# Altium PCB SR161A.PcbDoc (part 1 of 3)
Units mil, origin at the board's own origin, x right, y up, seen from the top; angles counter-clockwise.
Board outline 3150 x 3740 mil, 6 copper layers (Top Layer, Signal Layer 1, Signal Layer 2, Signal Layer 3, Signal Layer 4, Bottom Layer), stack 61.4 mil thick; 187 components, 70 nets, 452 pads, 384 vias.
Unrouted connection lines stored in the file: 5.
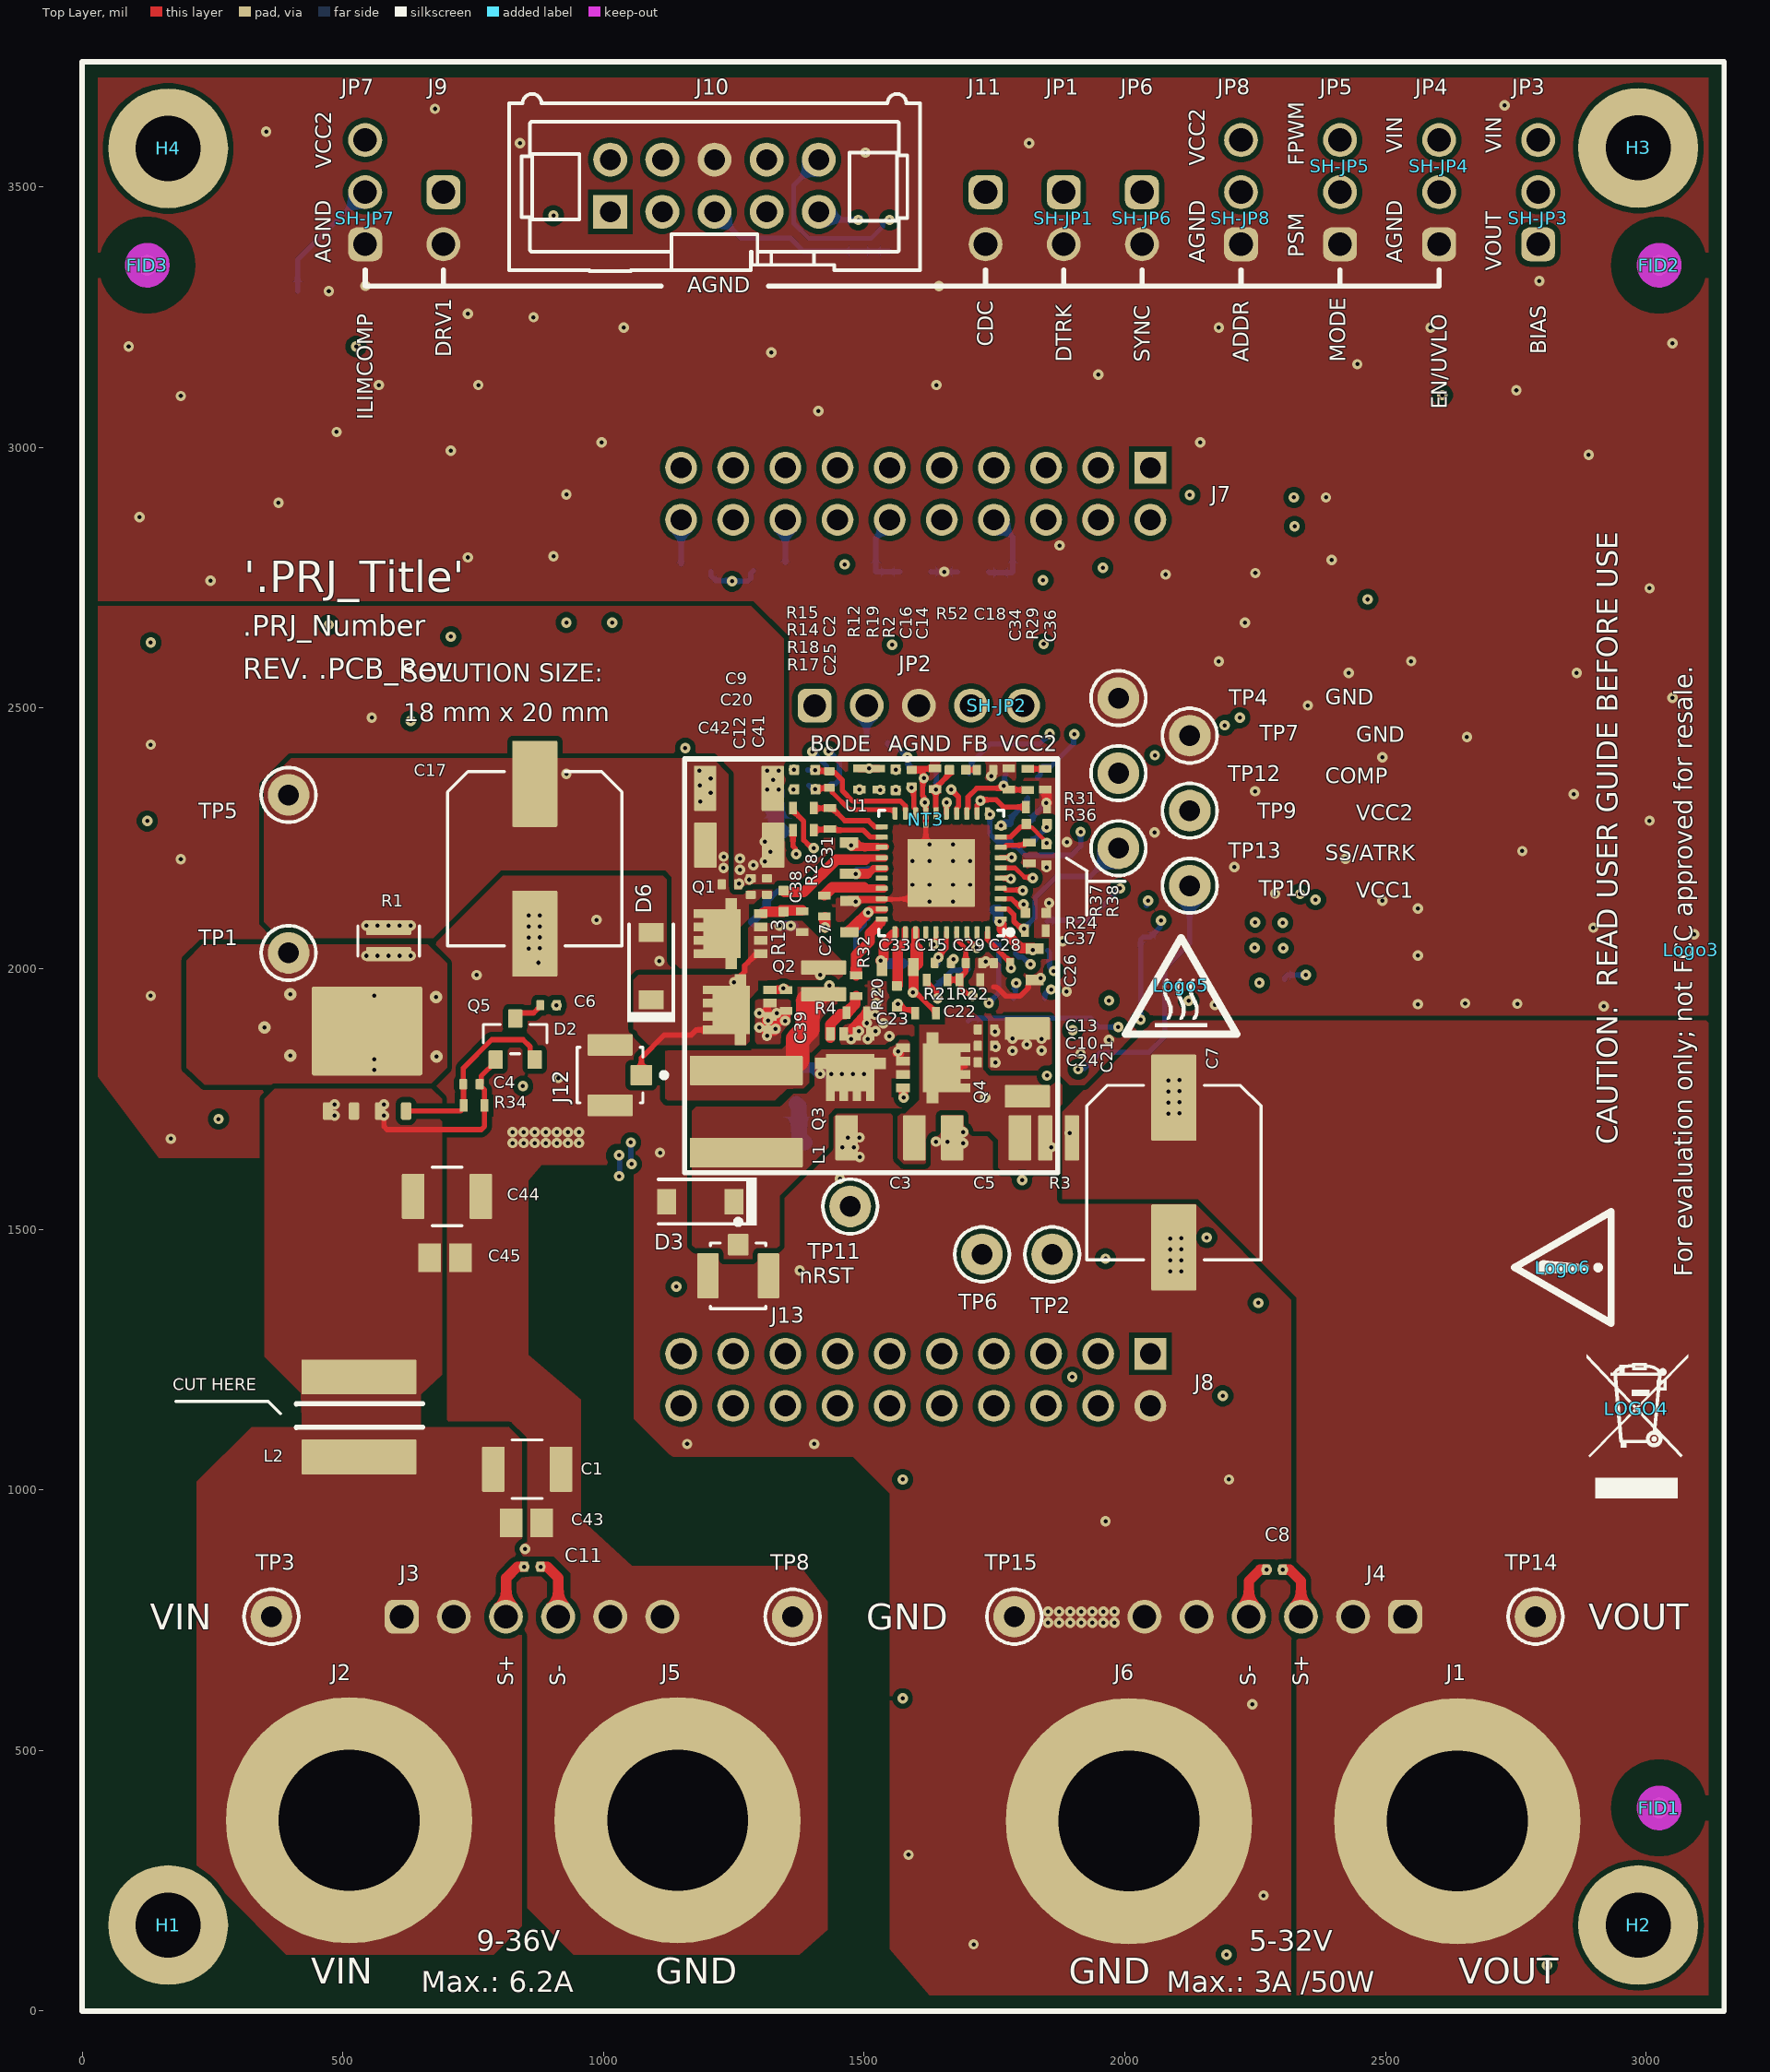
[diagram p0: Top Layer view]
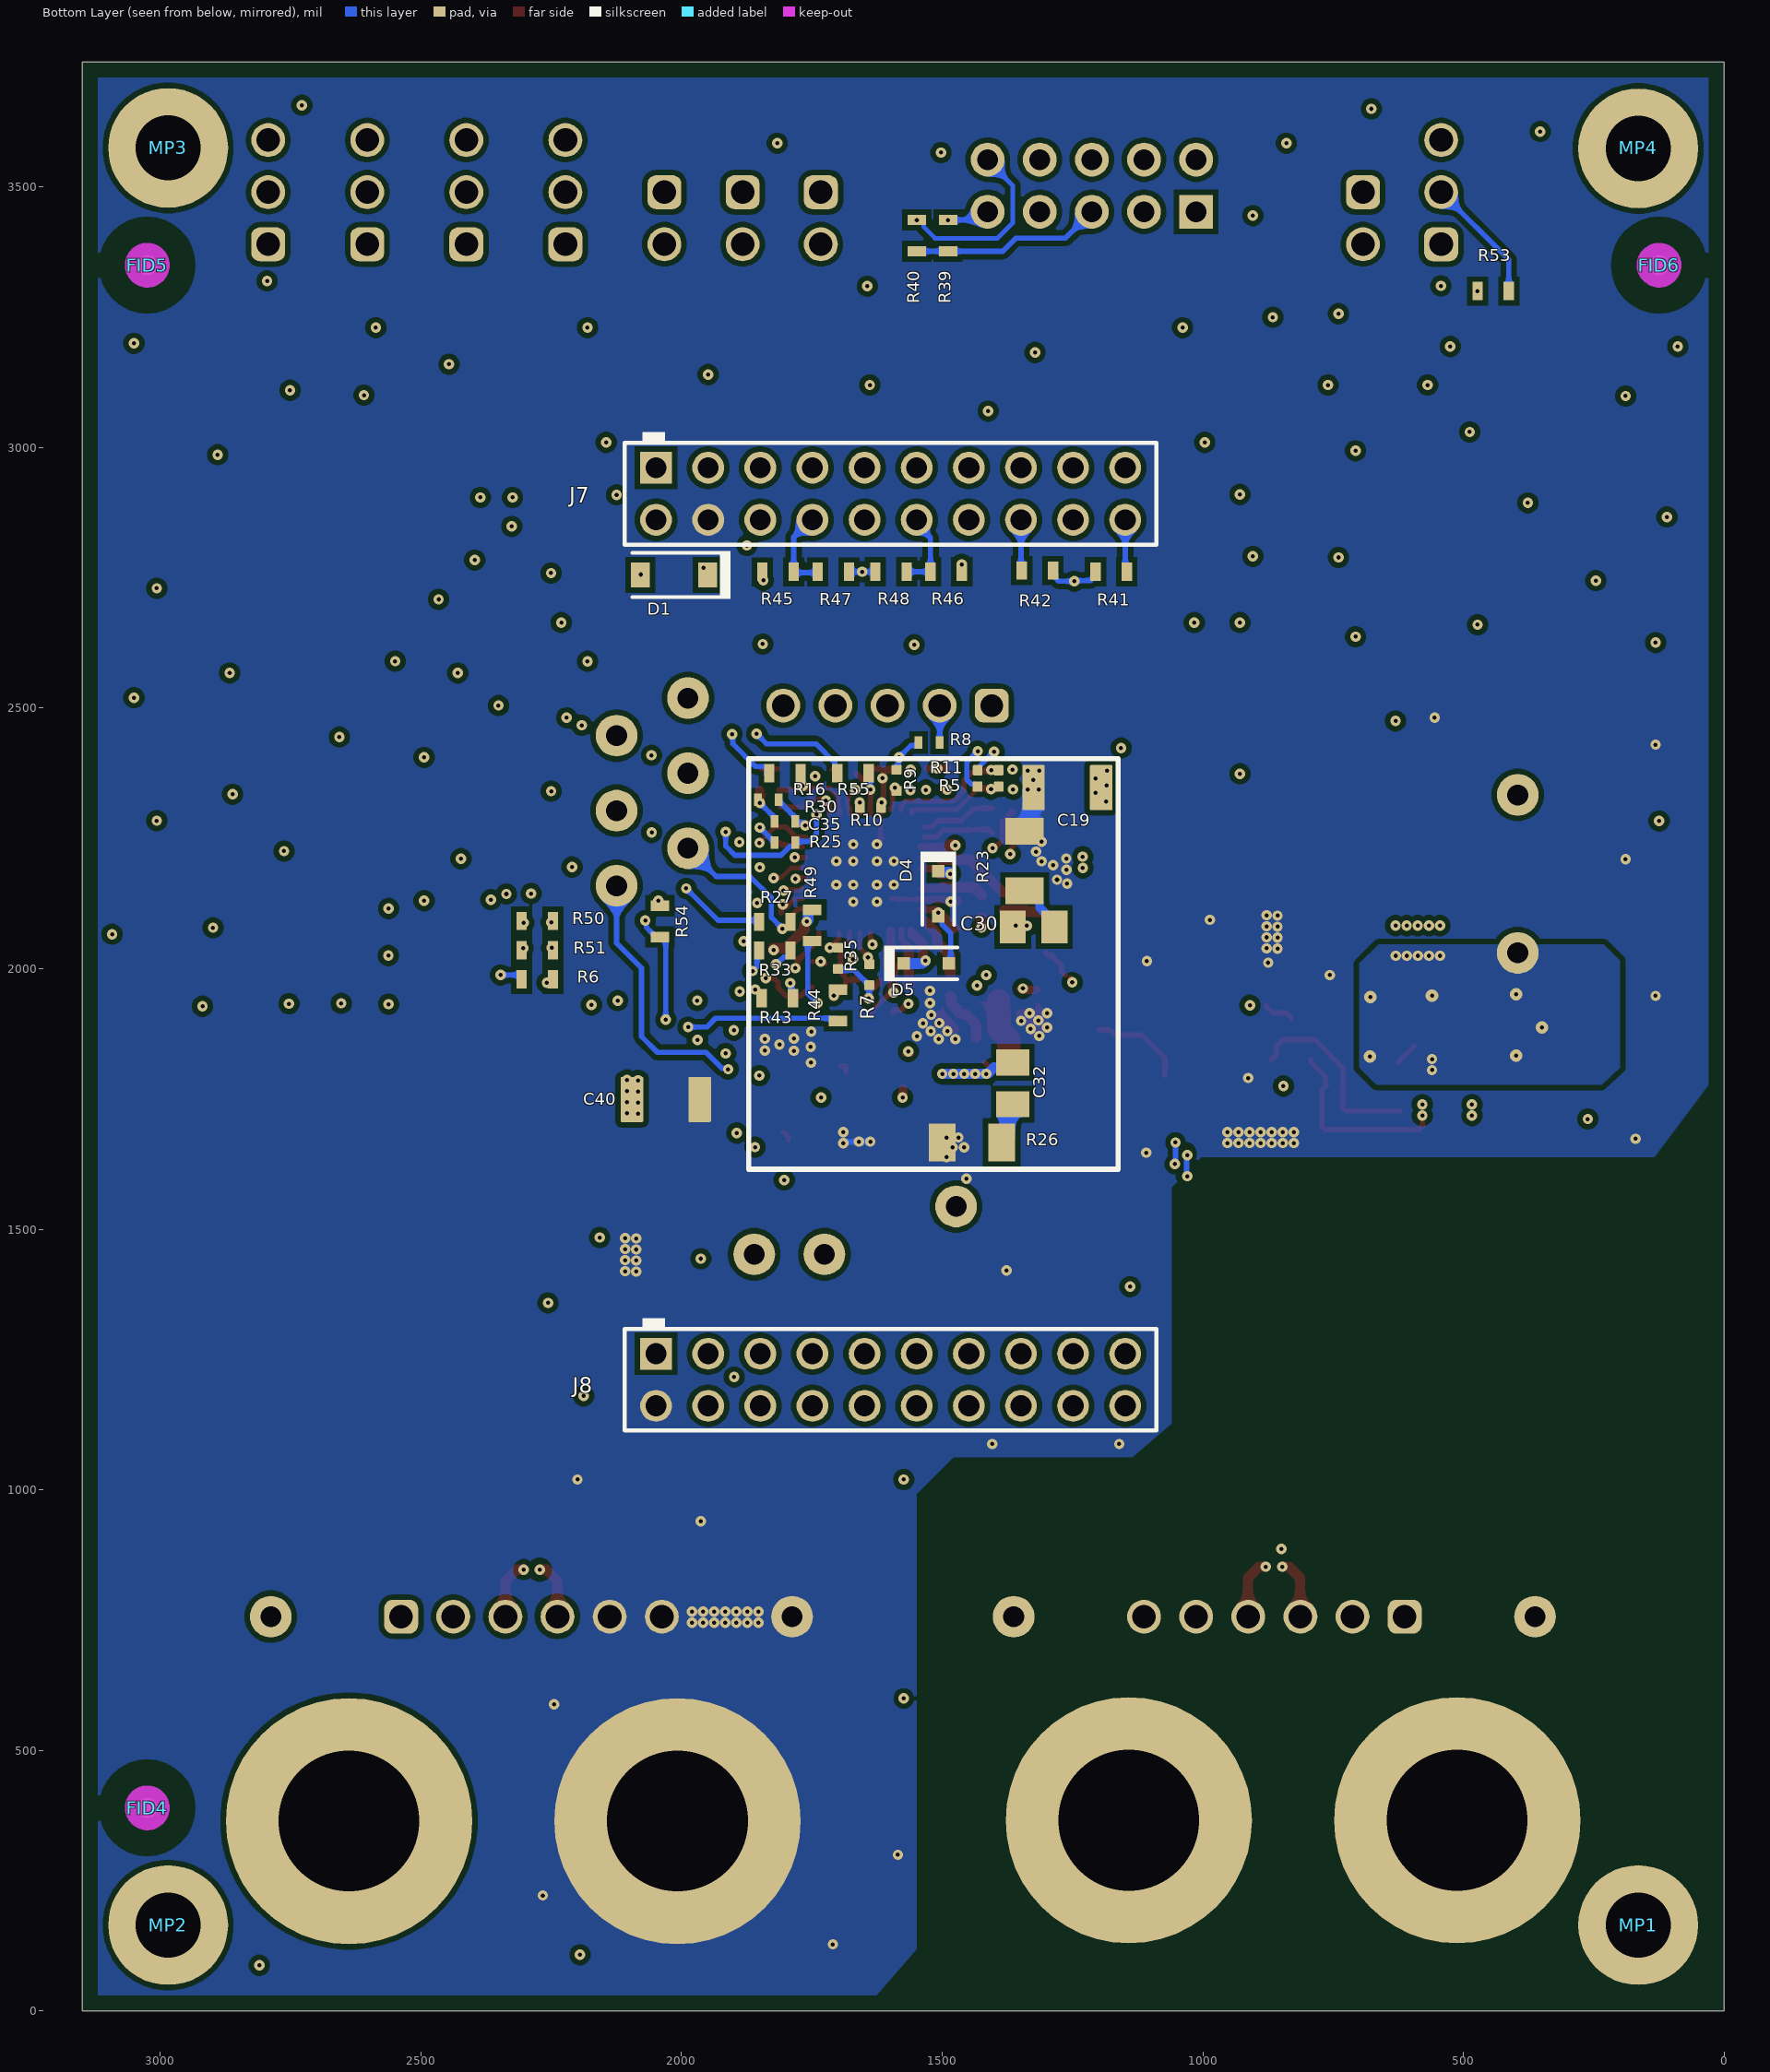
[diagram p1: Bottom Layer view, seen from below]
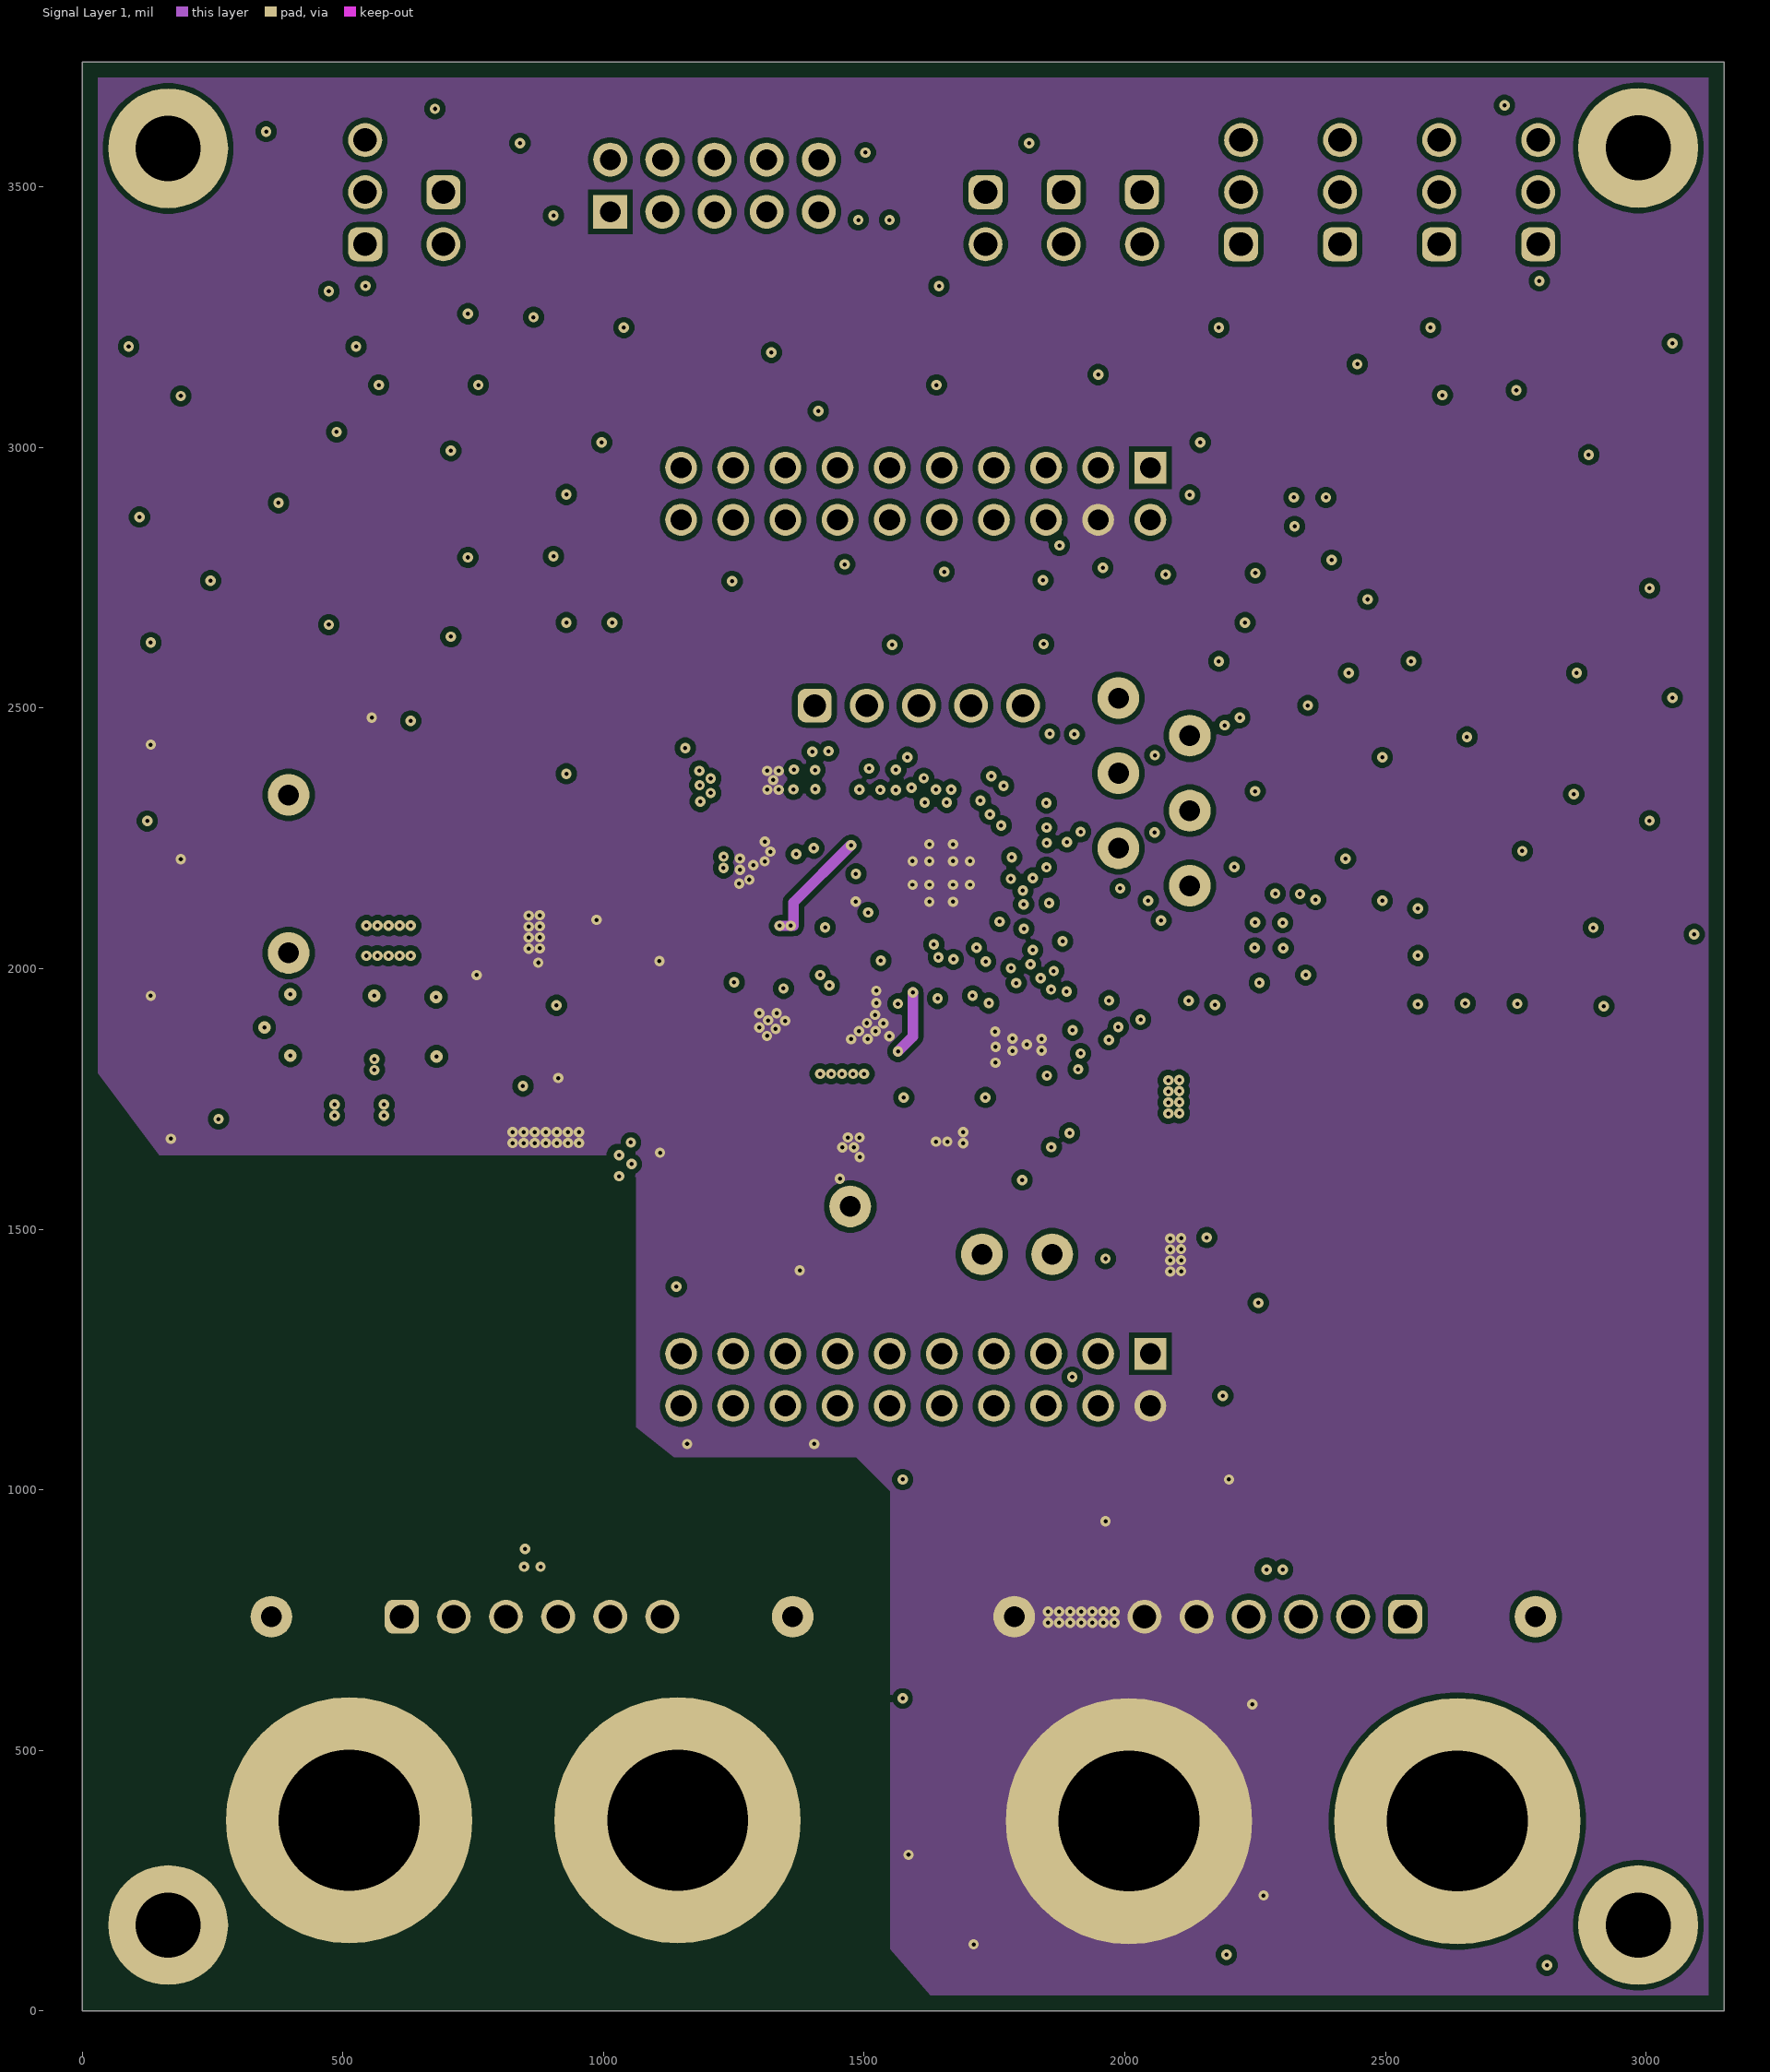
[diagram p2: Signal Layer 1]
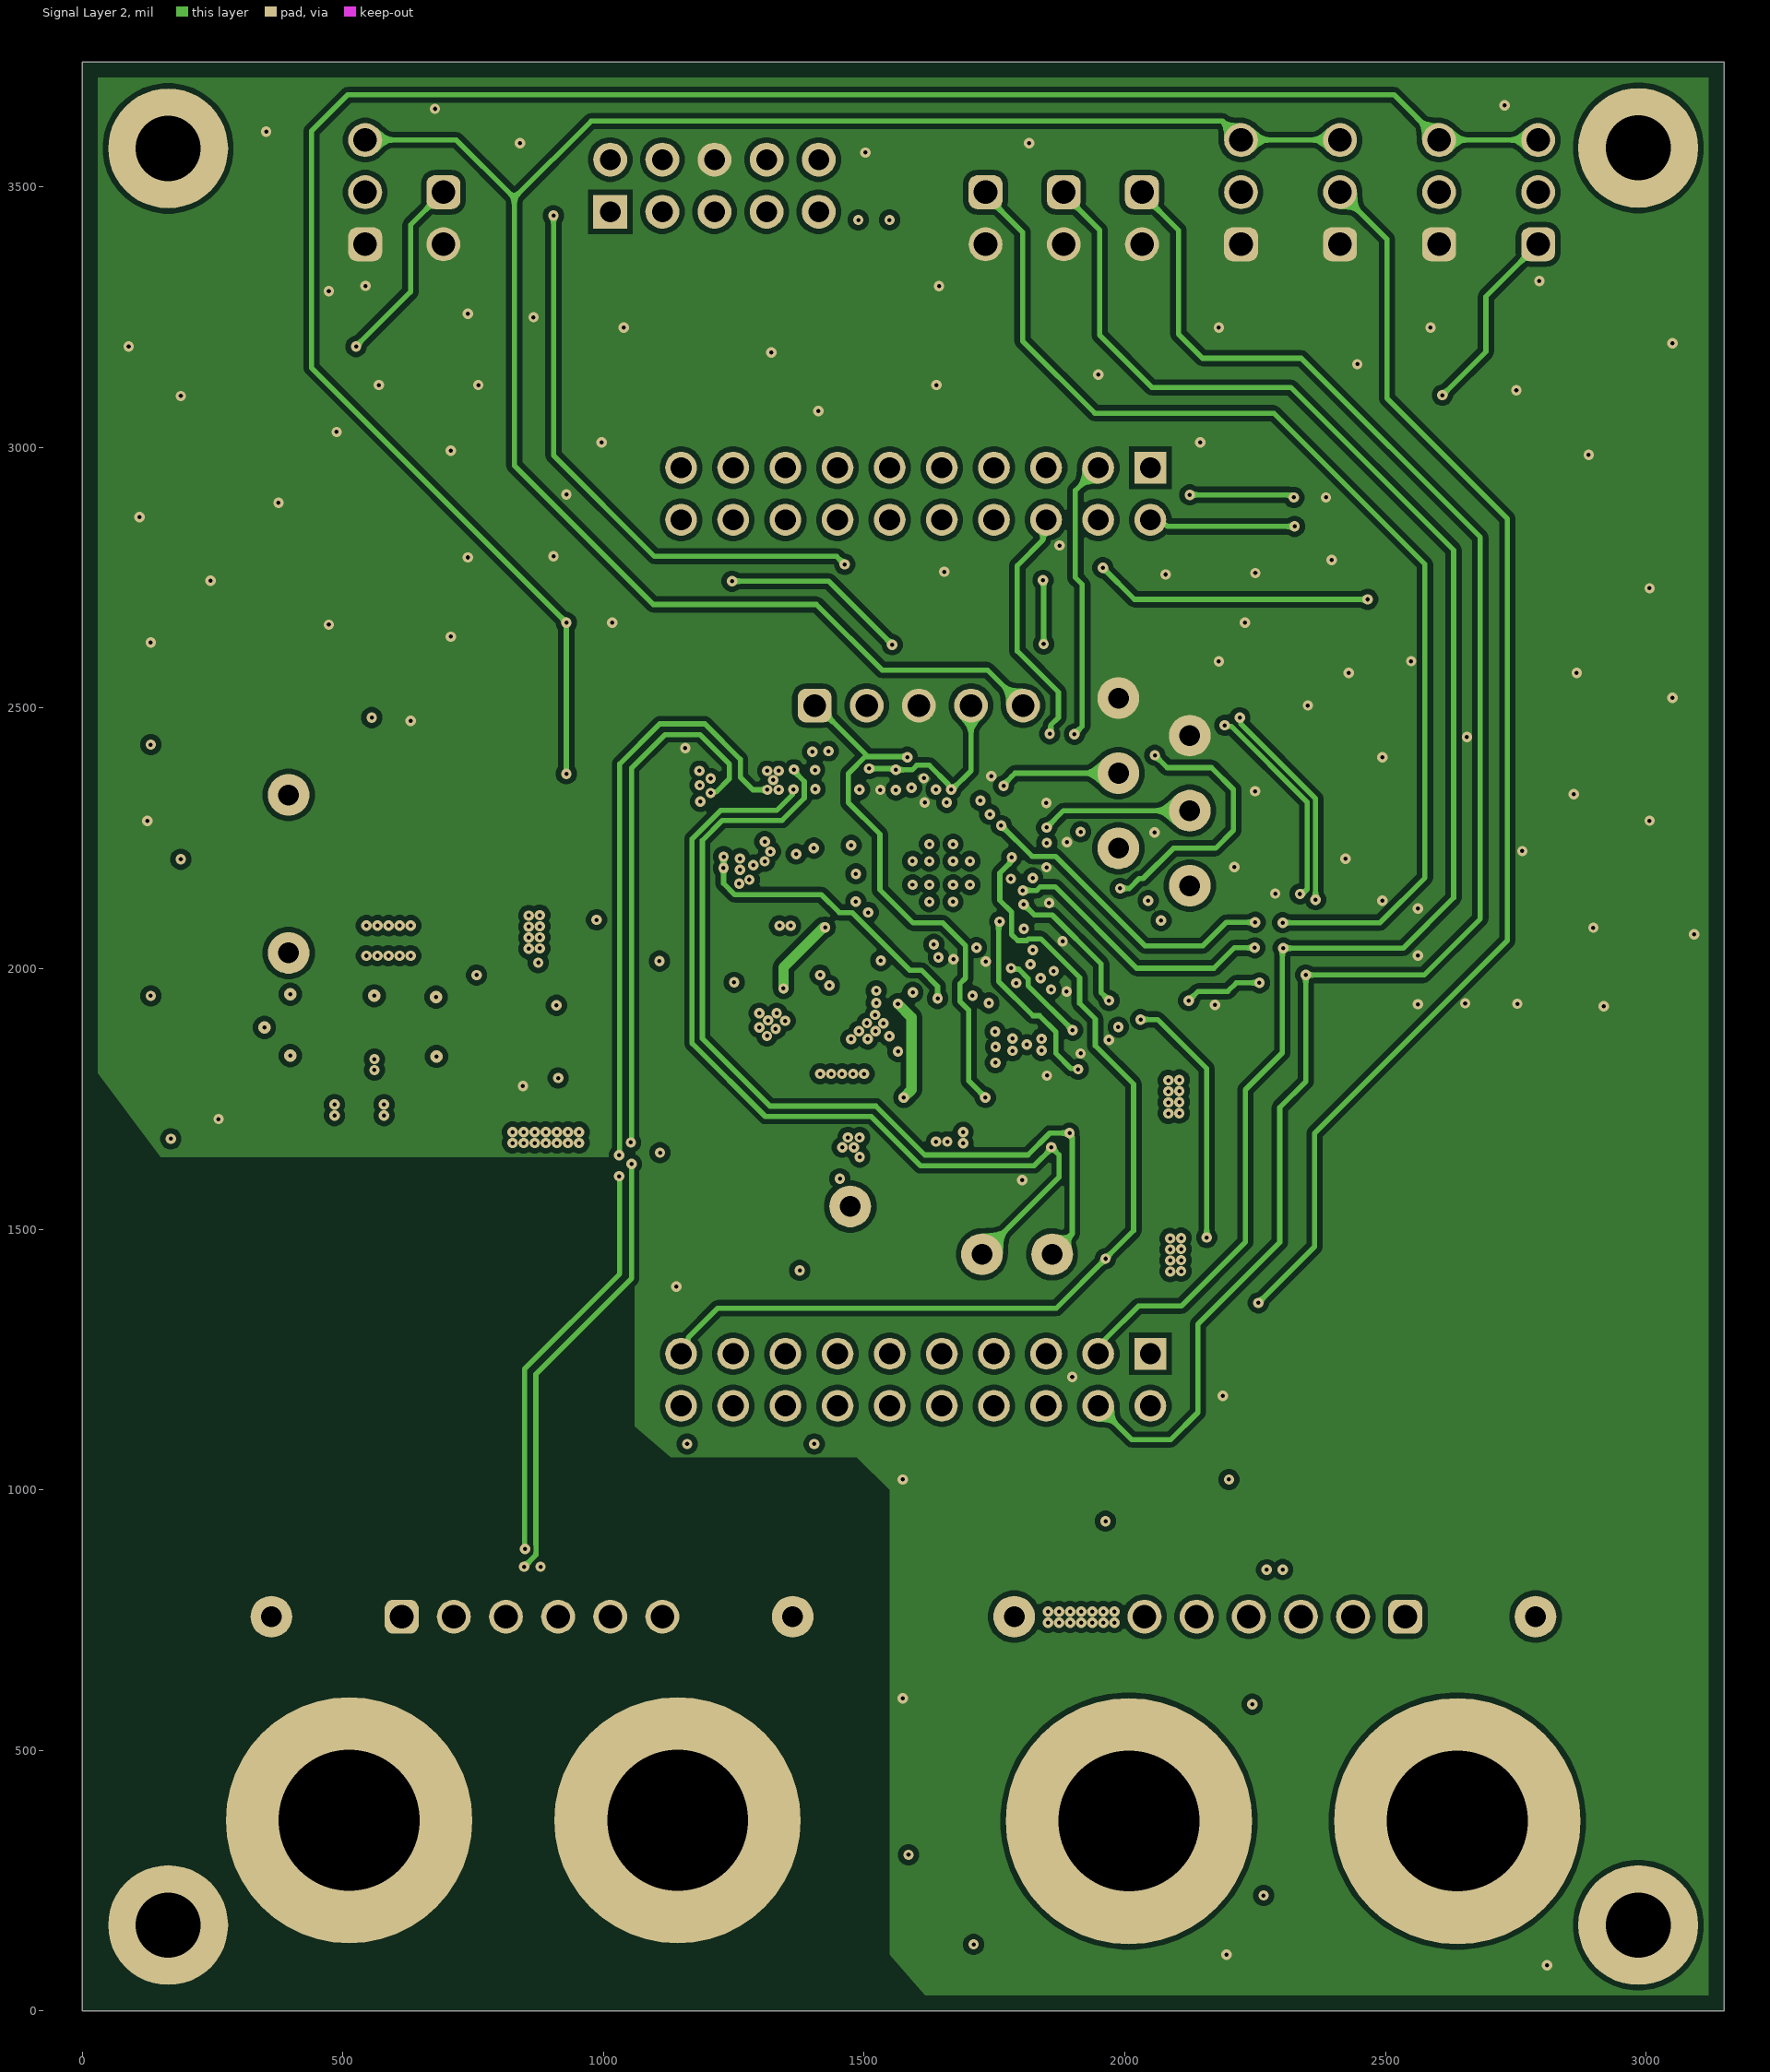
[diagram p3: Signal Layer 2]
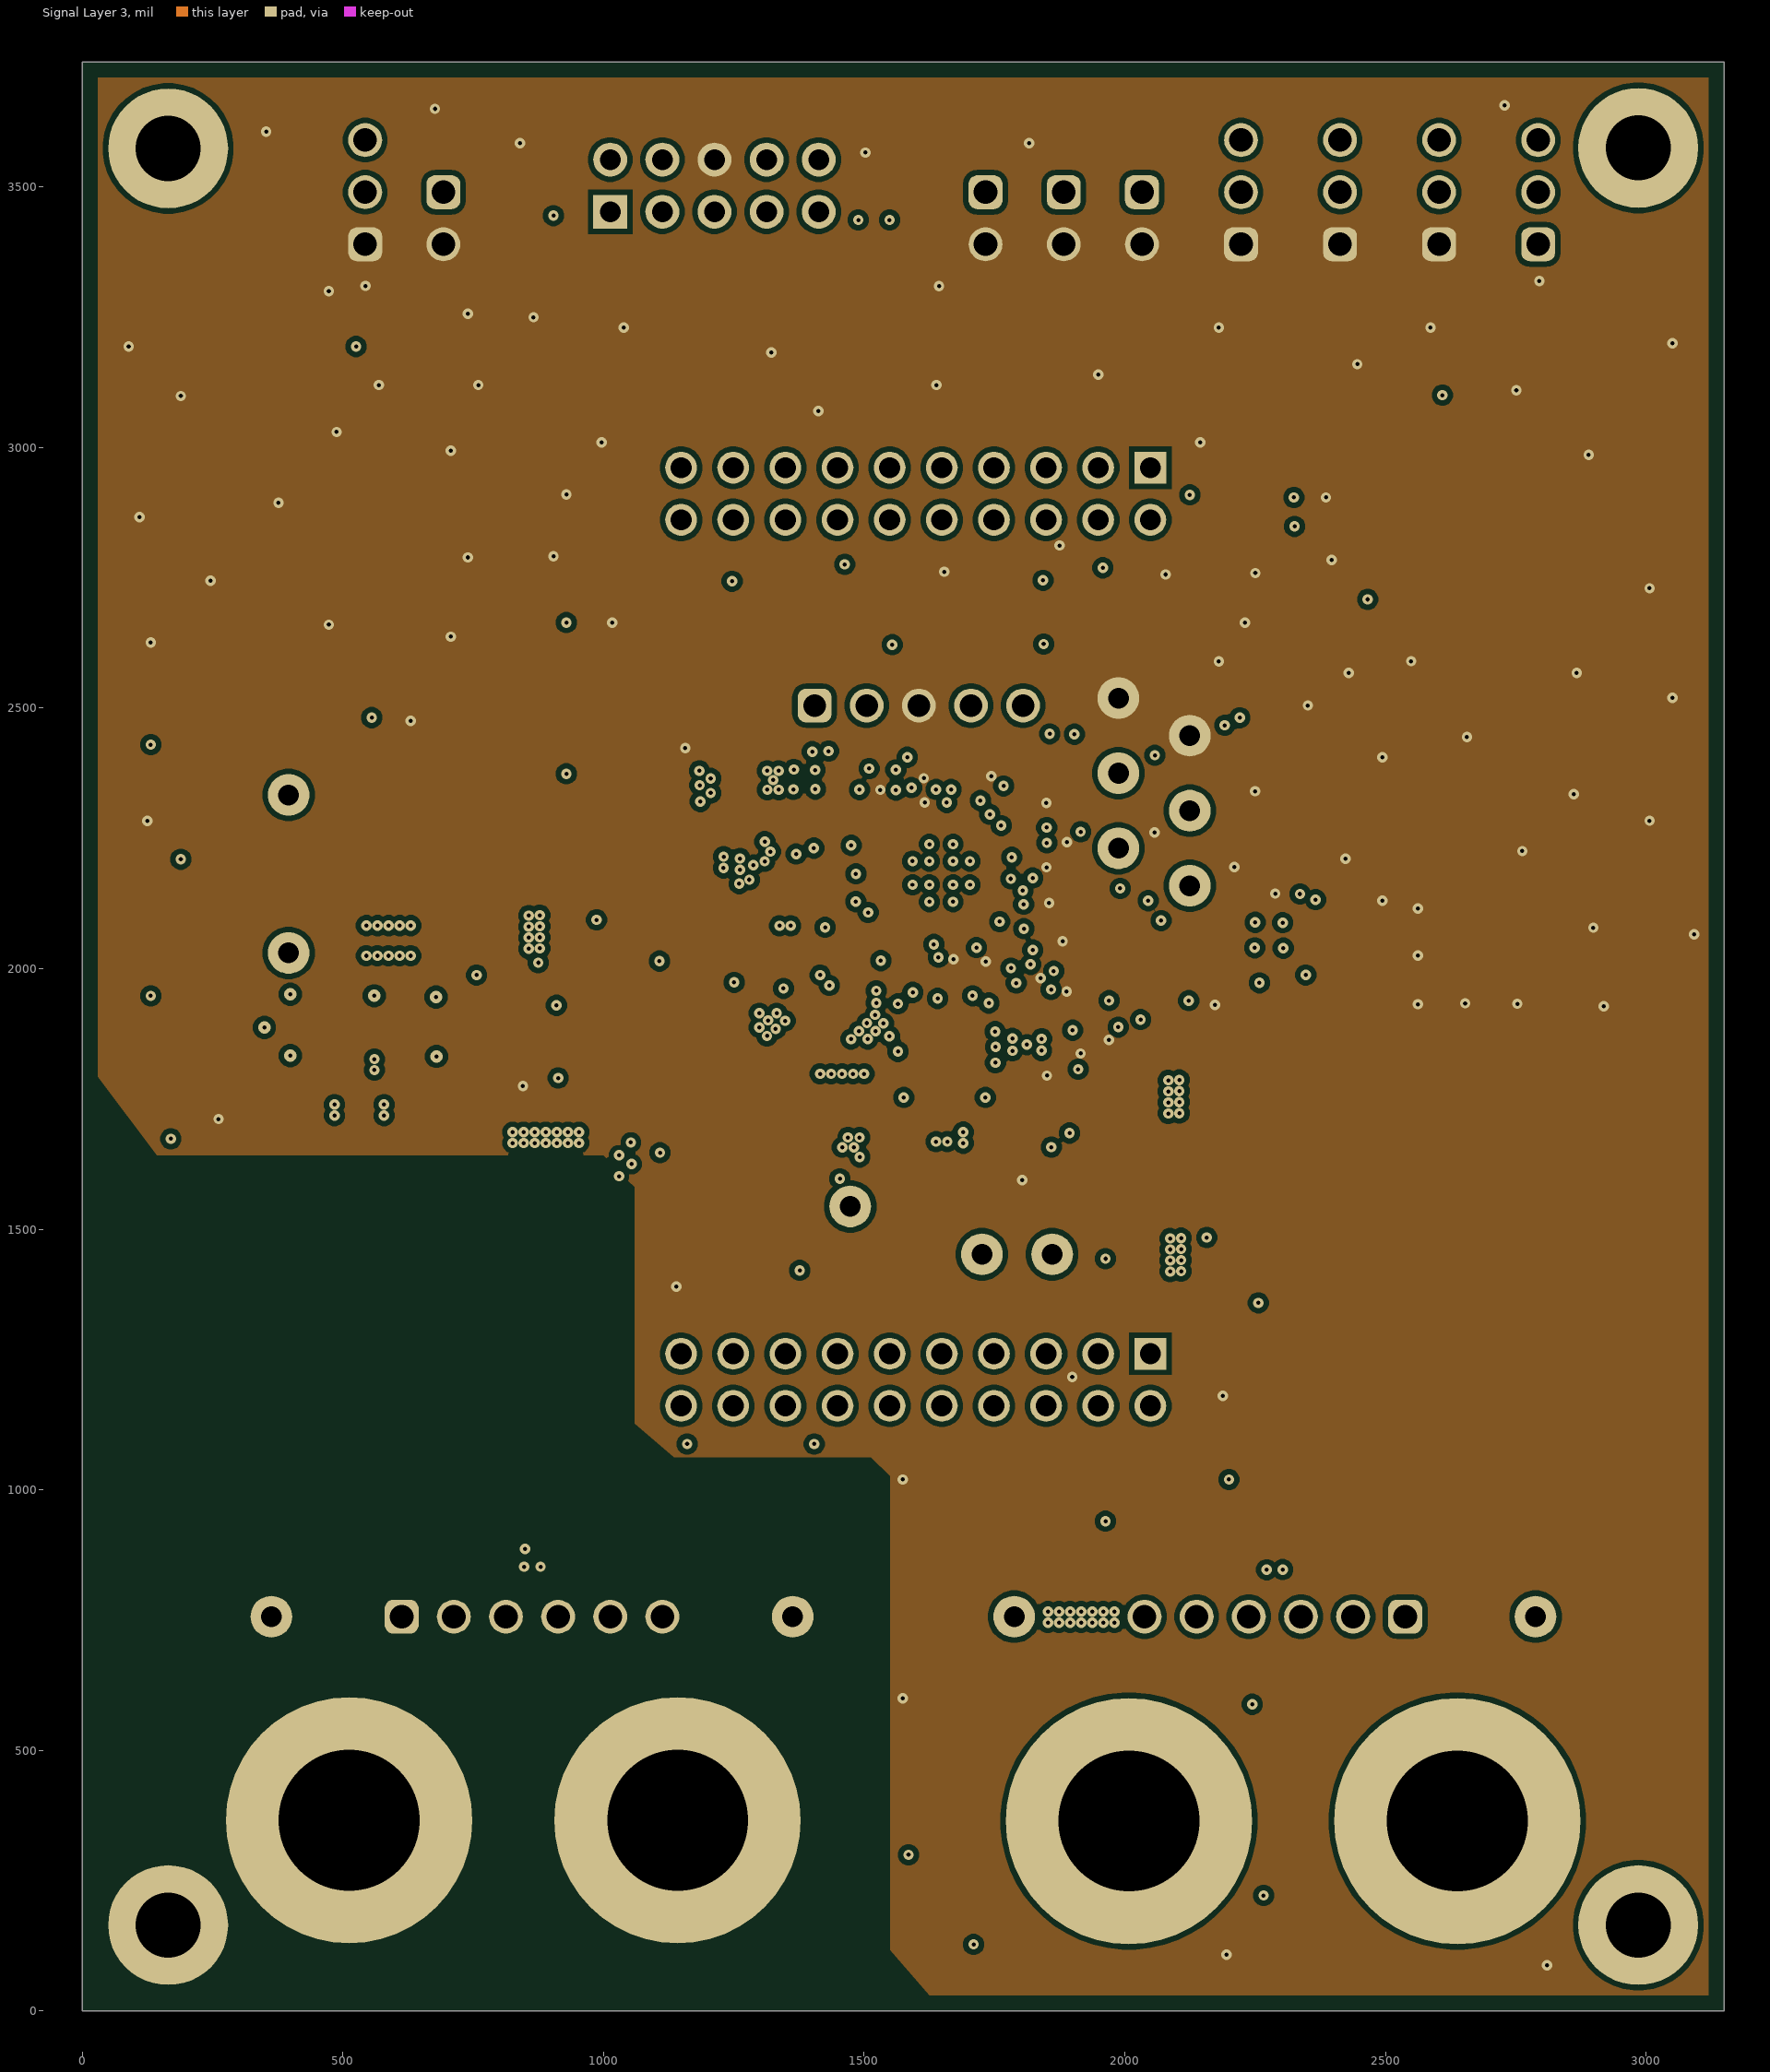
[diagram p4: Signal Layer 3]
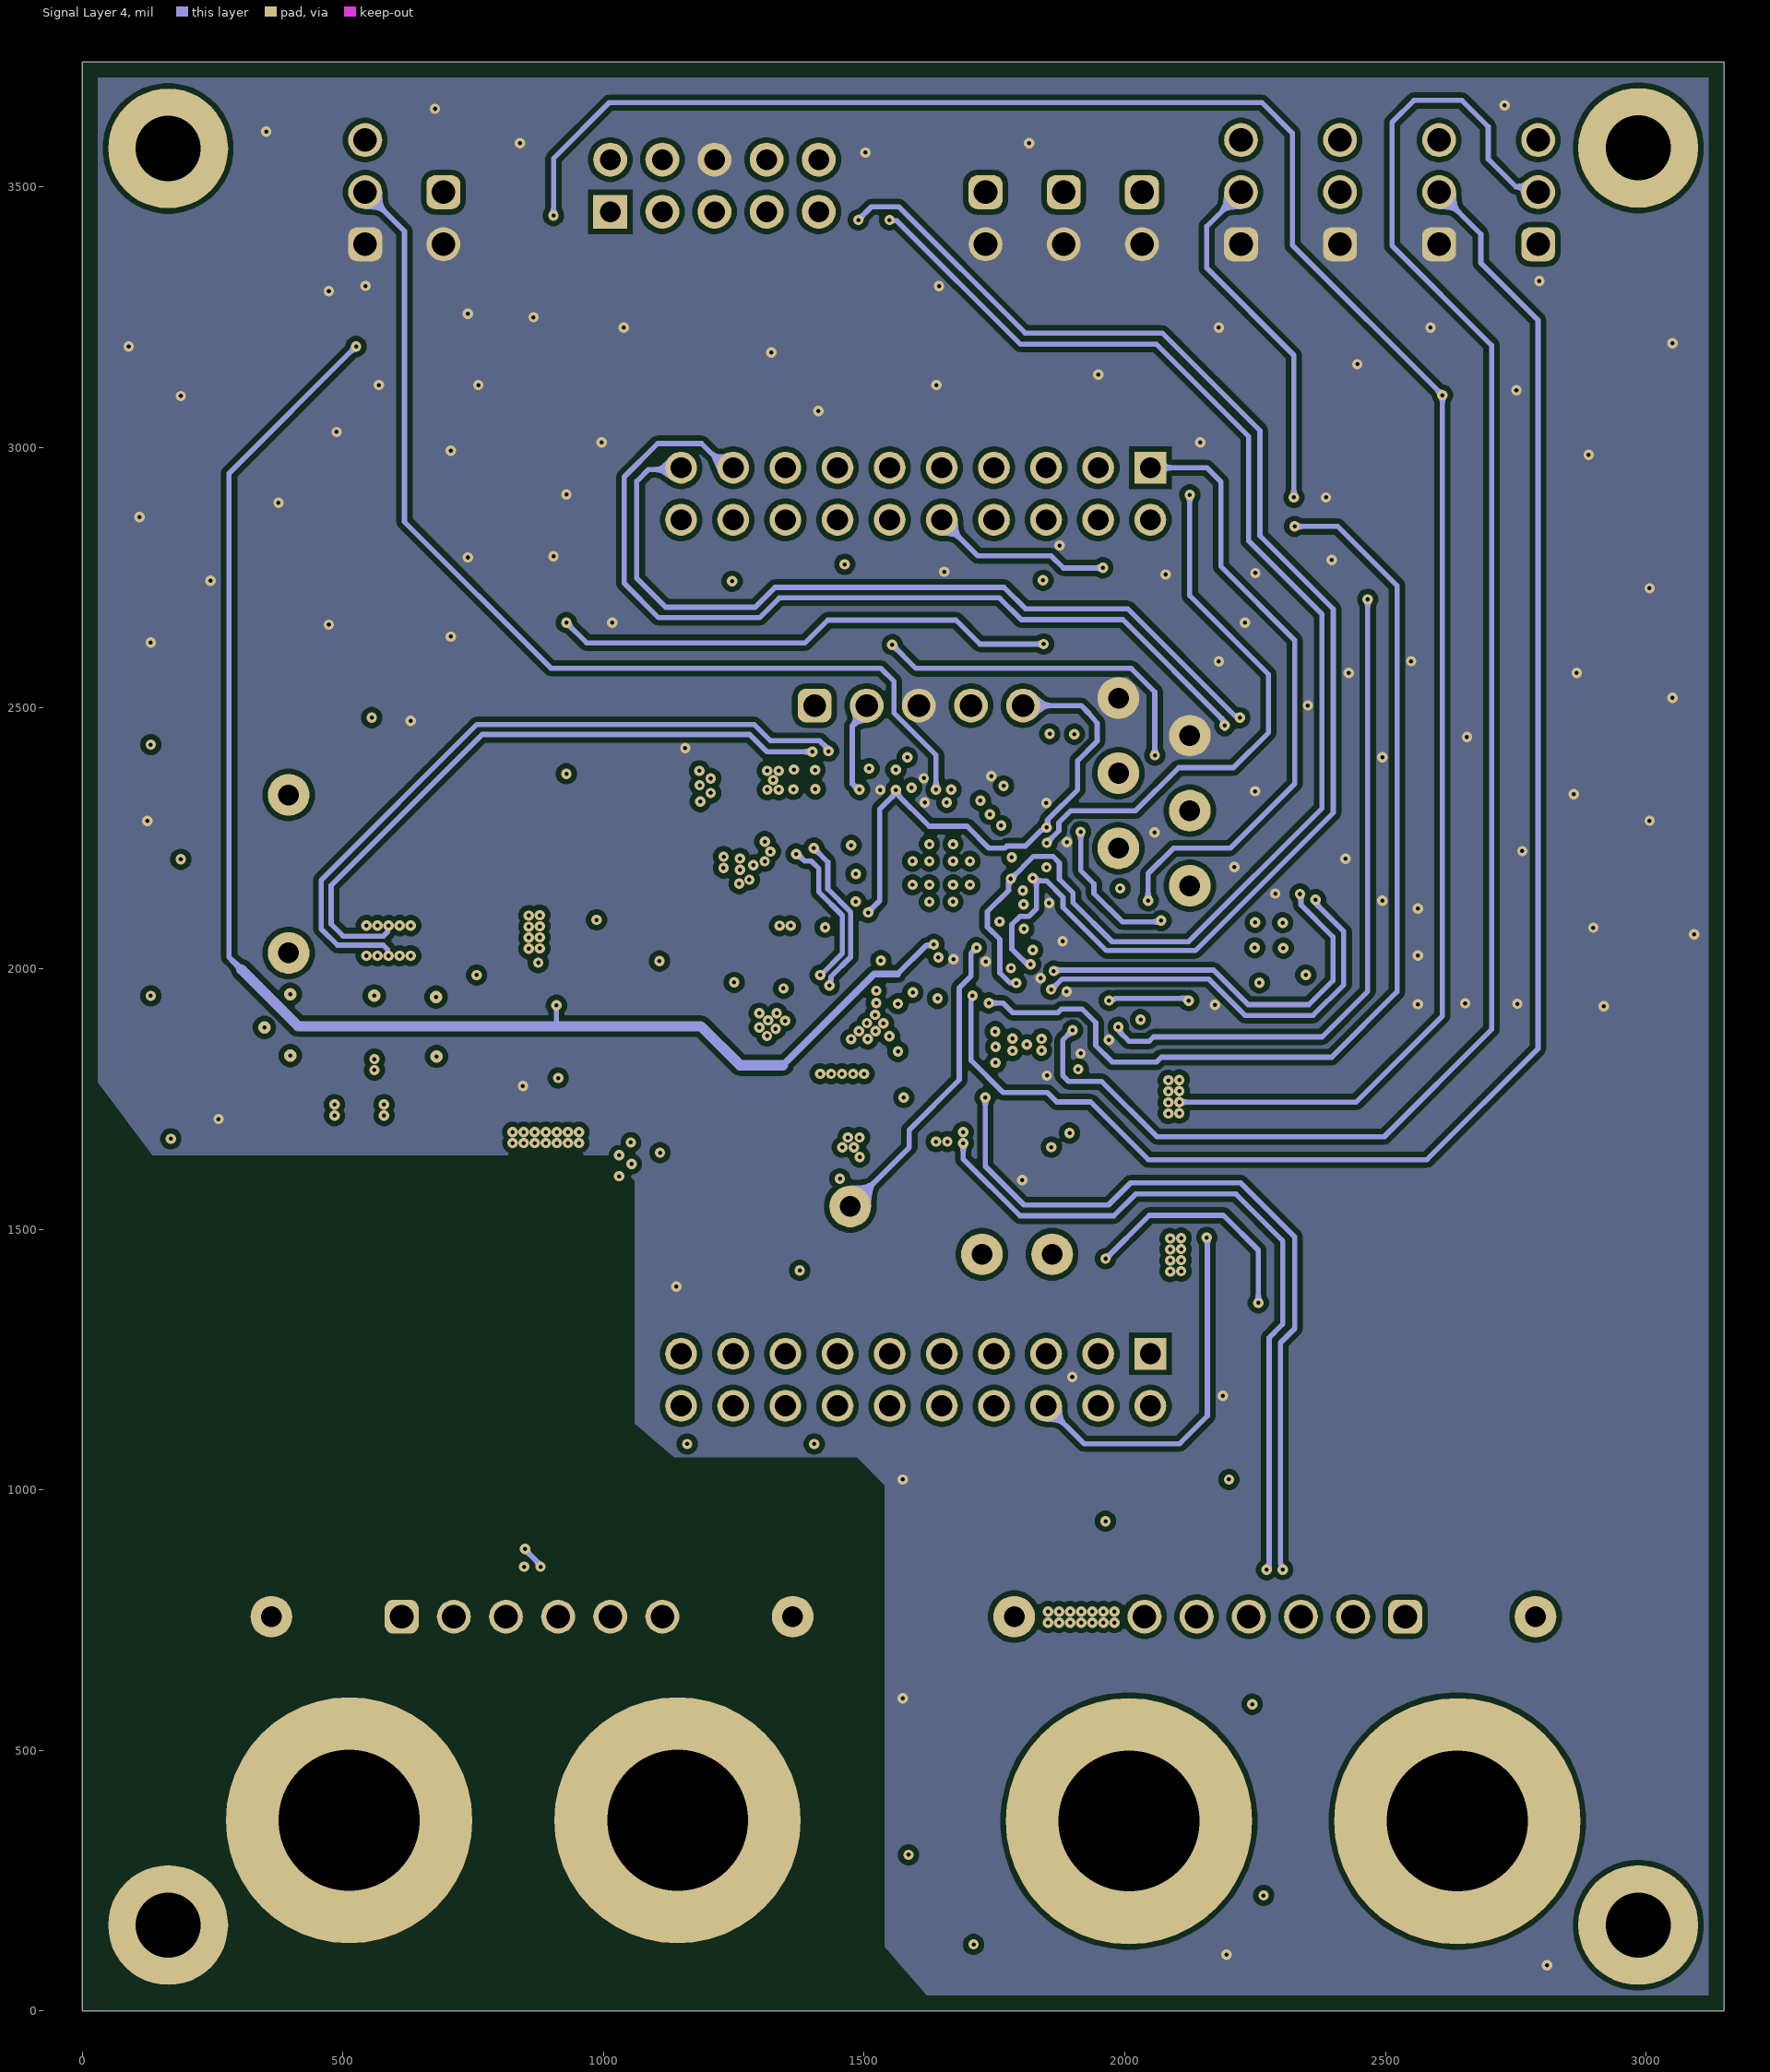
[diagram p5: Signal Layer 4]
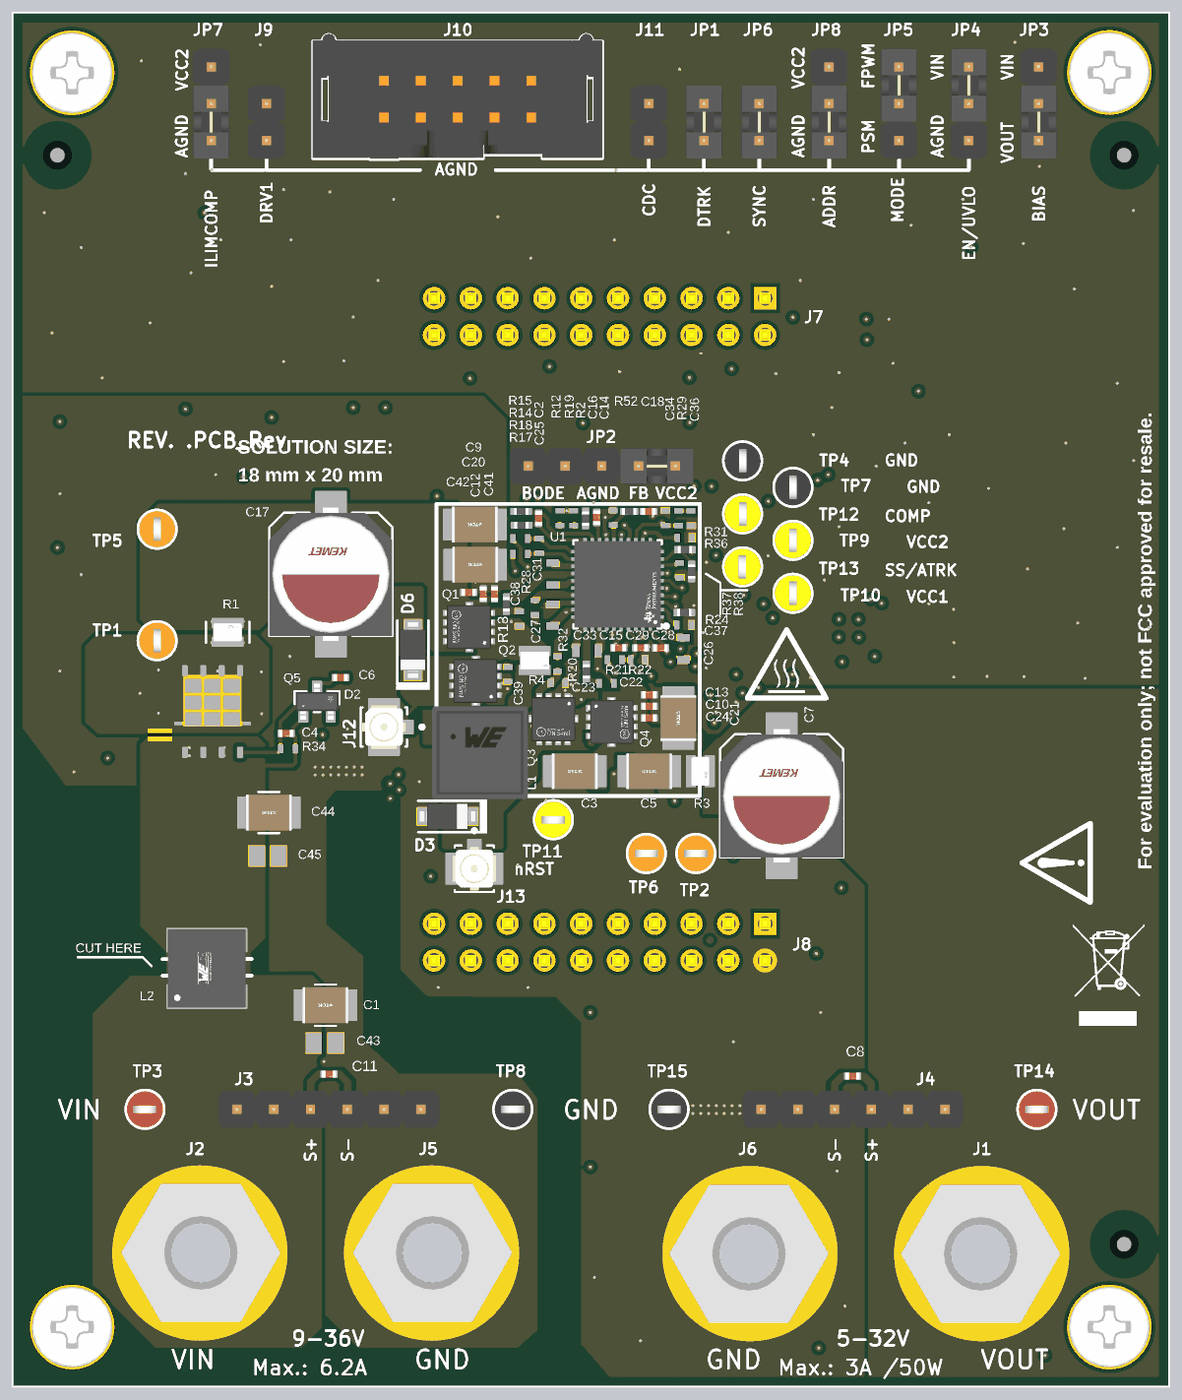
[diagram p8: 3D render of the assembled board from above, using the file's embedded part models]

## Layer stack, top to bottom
Top Solder: solder mask 0.5, Solder Resist, Dk 3.5
Top Layer: signal copper 2.8
Dielectric 1: prepreg 7, FR-4 High Tg, Dk 4.2
Signal Layer 1: signal copper 1.4
Dielectric 2: core 14, FR-4 High Tg, Dk 4.2
Signal Layer 2: signal copper 1.4
Dielectric 4: prepreg 8.2, FR-4 High Tg, Dk 4.2
Signal Layer 3: signal copper 1.4
Dielectric 5: core 14, FR-4 High Tg, Dk 4.2
Signal Layer 4: signal copper 1.4
Dielectric 3: prepreg 7, FR-4 High Tg, Dk 4.2
Bottom Layer: signal copper 2.8
Bottom Solder: solder mask 0.5, Solder Resist, Dk 3.5

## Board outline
0,0 0,3740 3150,3740 3150,0

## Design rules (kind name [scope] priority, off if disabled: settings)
AcuteAngle [All] p1: minimum=4.50000000000000E+0001 checktracksonly=FALSE
AssemblyTestPointUsage [All] p1: valid=2
BoardOutlineClearance BoardOutlineClearance_MountingHoles [OnCopper and InComponentClass('Mounting Holes')] p1: gap=30 ignorepadtopadclearanceinfootprint=FALSE
BoardOutlineClearance BoardOutlineClearance_Poly [OnCopper and InPoly] p2: gap=25 ignorepadtopadclearanceinfootprint=FALSE
BoardOutlineClearance [OnCopper and Not InComponentClass('Logo') and not InComponentClass('FiducialMark') and not InRegion(1000,500,4000,800)] p3: gap=30 ignorepadtopadclearanceinfootprint=FALSE
Clearance Clearance_FiducialMark [IsKeepOut and InComponentClass('FiducialMark') vs IsPad and InComponentClass('FiducialMark')] p1: gap=0 ignorepadtopadclearanceinfootprint=FALSE
Clearance Clearance_2 [InNetClass('HV') vs Not InNetClass('HV')] p2: gap=60 ignorepadtopadclearanceinfootprint=FALSE
Clearance Clearance_1 [InNetClass('MV') vs Not InNetClass('MV')] p3: gap=30 ignorepadtopadclearanceinfootprint=FALSE
Clearance Clearance_Keepouts [((IsTrack Or IsArc) And Not InPoly) And IsFree and IsKeepOut vs ((IsTrack Or IsArc) And Not InPoly) And IsFree and IsKeepOut] p4: gap=-1 ignorepadtopadclearanceinfootprint=FALSE
Clearance Clearance_BoardEdge_MountingHoles [OnCopper and InComponentClass('Mounting Holes') vs IsKeepOut] p5: gap=40 ignorepadtopadclearanceinfootprint=FALSE except(0: Arc-Hole Track-Hole SMDPad-Hole THPad-Hole Via-Hole Fill-Hole Poly-Hole Region-Hole Text-Hole)
Clearance Clearance_BoardEdge_Poly [OnCopper and InPoly vs IsKeepOut] p6: gap=50 ignorepadtopadclearanceinfootprint=FALSE except(0: Arc-Hole Track-Hole SMDPad-Hole THPad-Hole Via-Hole Fill-Hole Poly-Hole Region-Hole Text-Hole)
Clearance Clearance_BoardEdge [OnCopper and Not InComponentClass('Logo') and not InComponentClass('FiducialMark') and not InRegion(1000,500,4000,800) and Not IsKeepout vs IsKeepOut] p7: gap=50 ignorepadtopadclearanceinfootprint=FALSE
Clearance Clearance_Poly [InPolygon] p8: gap=10 ignorepadtopadclearanceinfootprint=FALSE
Clearance [All] p9: gap=6 ignorepadtopadclearanceinfootprint=FALSE except(0: Arc-Hole Track-Hole SMDPad-Hole THPad-Hole Via-Hole Fill-Hole Poly-Hole Region-Hole Text-Hole)
ComponentClearance ComponentClearance_1 [InComponent('NT3')  or InComponent('R29') or InComponent('R13')  or InComponent('R12')] p1: gap=-1 collisioncheckmode=3 verticalgap=-1 showdistances=FALSE
ComponentClearance ComponentClearance_MountingHoles_FiducialMarks [InComponentClass('Mounting Holes') vs InComponentClass('FiducialMark')] p2: gap=50 collisioncheckmode=3 verticalgap=10 showdistances=FALSE
ComponentClearance ComponentClearance_Shunt [InComponentClass('Header') vs InComponentClass('Shunt') or InComponent('SH-JP1') or InComponent('SH-JP2') or InComponent('SH-JP3') or InComponent('SH-JP4') or InComponent('SH-JP5') or InComponent('SH-JP6') or InComponent('SH-JP7') or InComponent('SH-JP8') or InComponent('SH-JP9') or InComponent('SH-JP10') or InComponent('SH-JP11') or InComponent('SH-JP12')] p3: gap=-1 collisioncheckmode=3 verticalgap=-1 showdistances=FALSE
ComponentClearance ComponentClearance_Logo [InComponentClass('Logo')] p4: gap=5 collisioncheckmode=3 verticalgap=10 showdistances=FALSE
ComponentClearance ComponentClearance_ScrewToNut [All vs (HasFootprint('Keystone_1902C'))  or InComponent('MP1') or InComponent('MP2') or  InComponent('MP3') or InComponent('MP4')  or (HasFootprint('NY PMS 440 0025 PH'))  or InComponent('H1') or InComponent('H2') or  InComponent('H3') or InComponent('H4')] p5: gap=5 collisioncheckmode=3 verticalgap=-1 showdistances=FALSE
ComponentClearance ComponentClearance_MountingHoles [InComponentClass('Mounting Holes')] p6: gap=100 collisioncheckmode=3 verticalgap=10 showdistances=FALSE
ComponentClearance ComponentClearance_SmallPassives [HasFootprint('0201*') or HasFootprint('0402*') or HasFootprint('0508') or HasFootprint('0603*') or HasFootprint('0612') or HasFootprint('0805*') or HasFootprint('0815*') or HasFootprint('0830*') or HasFootprint('1206*') or HasFootprint('1210*') or HasFootprint('1808*') or HasFootprint('1812*') or HasFootprint('1825*') or HasFootprint('2010*') or HasFootprint('2220*') or HasFootprint('2225*') or HasFootprint('2512*') or HasFootprint('2728*') or HasFootprint('3518*') vs HasFootprint('0201*') or HasFootprint('0402*') or HasFootprint('0508') or HasFootprint('0603*') or HasFootprint('0612') or HasFootprint('0805*') or HasFootprint('0815*') or HasFootprint('0830*') or HasFootprint('1206*') or HasFootprint('1210*') or HasFootprint('1808*') or HasFootprint('1812*') or HasFootprint('1825*') or HasFootprint('2010*') or HasFootprint('2220*') or HasFootprint('2225*') or HasFootprint('2512*') or HasFootprint('2728*') or HasFootprint('3518*')] p7: gap=17.5 collisioncheckmode=3 verticalgap=17.5 showdistances=FALSE
ComponentClearance ComponentClearance_THtoSMT [IsThruComponent vs IsSMTComponent] p8: gap=10 collisioncheckmode=3 verticalgap=10 showdistances=FALSE
ComponentClearance ComponentClearance_THtoTH [IsThruComponent vs IsThruComponent] p9: gap=20 collisioncheckmode=3 verticalgap=20 showdistances=FALSE
ComponentClearance [All] p10: gap=10 collisioncheckmode=3 verticalgap=10 showdistances=FALSE
DiffPairsRouting [All] p1: maxlimit=100 minlimit=10 mostfreqgap=10 toplayer_minwidth=15 toplayer_maxwidth=15 toplayer_prefwidth=15 midlayer1_minwidth=15 midlayer1_maxwidth=15 midlayer1_prefwidth=15 midlayer2_minwidth=15 midlayer2_maxwidth=15 midlayer2_prefwidth=15 midlayer3_minwidth=15 midlayer3_maxwidth=15 midlayer3_prefwidth=15 midlayer4_minwidth=15 midlayer4_maxwidth=15 midlayer4_prefwidth=15 bottomlayer_minwidth=15 bottomlayer_maxwidth=15 bottomlayer_prefwidth=15 maxuncoupledlength=1000
FabricationTestPointUsage TestPointUsage [All] p1: valid=2 allowmultiple=FALSE
FabricationTestpoint Testpoint [All] p1: side=3 testpointundercomponent=TRUE minsize=40 maxsize=100 preferedsize=60 minholesize=0 maxholesize=40 preferedholesize=32 testpointgrid=1 allowsidetop=TRUE allowsidebottom=TRUE usegrid=TRUE gridtolerance=0.01
FanoutControl Fanout_LCC [IsLCC] p1: bgadir=Out bgaviamode=Centered fanoutstyle=Auto fanoutdirection=Alternating viagrid=1 // Fanout_LCC (Default Rule)
FanoutControl Fanout_BGA [IsBGA] p2: bgadir=Out bgaviamode=Centered fanoutstyle=Auto fanoutdirection=Alternating viagrid=1 // Fanout_BGA (Default Rule)
FanoutControl Fanout_Default [All] p4: bgadir=Out bgaviamode=Centered fanoutstyle=Auto fanoutdirection=Alternating viagrid=1 // Fanout_Default (Default Rule)
FanoutControl Fanout_Small [(CompPinCount < 5)] p5: bgadir=Out bgaviamode=Centered fanoutstyle=Auto fanoutdirection=OutThenIn viagrid=1 // Fanout_Small (Default Rule)
Height [All] p1: minheight=0 maxheight=3000 prefheight=500
HoleSize [All] p1: absolutevalues=TRUE maxlimit=280 minlimit=7.87 maxpercent=80.000 minpercent=20.000
MinimumAnnularRing MinimumAnnularRing_ThermalPadVias [IsVia and InAnyComponent] p1: minimumring=5.91
MinimumAnnularRing [All] p2: minimumring=6
MinimumSolderMaskSliver MinimumSolderMaskSliver_Logo [InComponentClass('Logo') vs InComponentClass('Logo')] p1: minsoldermaskwidth=0.7
MinimumSolderMaskSliver [All] p2: minsoldermaskwidth=3.94
PlaneConnect [All] p1: planeconnectstyle=Direct reliefexpansion=10 reliefentries=4 reliefconductorwidth=10 reliefairgap=10
PolygonConnect PolygonConnect_15 [All vs IsNamedPolygon('C109_2') Or  IsNamedPolygon('C107_2') Or  IsNamedPolygon('HV') Or  IsNamedPolygon('Q203_5') Or  IsNamedPolygon('C107_2') Or  IsNamedPolygon('HS') Or  IsNamedPolygon('Q201_5') Or  IsNamedPolygon('Q203_5') Or  IsNamedPolygon('C106_2') Or  IsNamedPolygon('C108_2') Or  IsNamedPolygon('Vout') Or  IsNamedPolygon('Q203_5') Or  IsNamedPolygon('C108_2') Or  IsNamedPolygon('C113_2') Or  IsNamedPolygon('Q203_5') Or  IsNamedPolygon('Q201_5') Or  IsNamedPolygon('C107_2') Or  IsNamedPolygon('C102_1') Or  IsNamedPolygon('SGND') Or  IsNamedPolygon('GND') Or  IsNamedPolygon('SGND') Or  IsNamedPolygon('GND') Or  IsNamedPolygon('IN+') Or  IsNamedPolygon('IN+') Or  IsNamedPolygon('Q201_5') Or  IsNamedPolygon('Q201_5') Or  IsNamedPolygon('SGND') Or  IsNamedPolygon('SGND') Or  IsNamedPolygon('Vout') Or  IsNamedPolygon('Vout') Or  IsNamedPolygon('IN+') Or  IsNamedPolygon('GND') Or  IsNamedPolygon('IN+') Or  IsNamedPolygon('GND')] p1: connectstyle=Direct reliefconductorwidth=10 reliefentries=4 polygonreliefangle="90 Angle" airgapwidth=10
PolygonConnect PolygonConnect_14 [All vs IsNamedPolygon('C106_2') Or  IsNamedPolygon('C107_2') Or  IsNamedPolygon('C107_2') Or  IsNamedPolygon('C107_2') Or  IsNamedPolygon('C102_1') Or  IsNamedPolygon('Q203_5') Or  IsNamedPolygon('Vout') Or  IsNamedPolygon('Q203_5') Or  IsNamedPolygon('Q203_5') Or  IsNamedPolygon('Q201_5') Or  IsNamedPolygon('C108_2') Or  IsNamedPolygon('Q203_5') Or  IsNamedPolygon('HS') Or  IsNamedPolygon('HV') Or  IsNamedPolygon('C108_2') Or  IsNamedPolygon('Q201_5') Or  IsNamedPolygon('C109_2') Or  IsNamedPolygon('Q201_5') Or  IsNamedPolygon('Q201_5') Or  IsNamedPolygon('C113_2')] p2: connectstyle=Direct reliefconductorwidth=10 reliefentries=4 polygonreliefangle="90 Angle" airgapwidth=10
PolygonConnect PolygonConnect_13 [All vs IsNamedPolygon('C102_1') Or  IsNamedPolygon('HV') Or  IsNamedPolygon('C107_2') Or  IsNamedPolygon('C109_2') Or  IsNamedPolygon('C107_2') Or  IsNamedPolygon('C108_2') Or  IsNamedPolygon('C106_2') Or  IsNamedPolygon('C108_2') Or  IsNamedPolygon('C113_2') Or  IsNamedPolygon('C107_2')] p3: connectstyle=Direct reliefconductorwidth=10 reliefentries=4 polygonreliefangle="90 Angle" airgapwidth=10
PolygonConnect PolygonConnect_12 [All vs IsNamedPolygon('C107_2') Or  IsNamedPolygon('C113_2') Or  IsNamedPolygon('C106_2') Or  IsNamedPolygon('C107_2') Or  IsNamedPolygon('C107_2') Or  IsNamedPolygon('C102_1')] p4: connectstyle=Direct reliefconductorwidth=10 reliefentries=4 polygonreliefangle="90 Angle" airgapwidth=10
PolygonConnect PolygonConnect_11 [All vs IsNamedPolygon('C106_2') Or  IsNamedPolygon('C102_1') Or  IsNamedPolygon('C107_2') Or  IsNamedPolygon('C107_2') Or  IsNamedPolygon('C107_2')] p5: connectstyle=Direct reliefconductorwidth=10 reliefentries=4 polygonreliefangle="90 Angle" airgapwidth=10
PolygonConnect PolygonConnect_10 [All vs IsNamedPolygon('C106_2')] p6: connectstyle=Direct reliefconductorwidth=10 reliefentries=4 polygonreliefangle="90 Angle" airgapwidth=10
PolygonConnect PolygonConnect_9 [All vs IsNamedPolygon('C11_1') Or  IsNamedPolygon('Vin') Or  IsNamedPolygon('Vin') Or  IsNamedPolygon('5V') Or  IsNamedPolygon('D6_2') Or  IsNamedPolygon('Q3_3') Or  IsNamedPolygon('GND2') Or  IsNamedPolygon('GND2') Or  IsNamedPolygon('GND') Or  IsNamedPolygon('Q3_4') Or  IsNamedPolygon('12V5') Or  IsNamedPolygon('GND') Or  IsNamedPolygon('12V5') Or  IsNamedPolygon('D3_1')] p7: connectstyle=Direct reliefconductorwidth=10 reliefentries=4 polygonreliefangle="90 Angle" airgapwidth=10
PolygonConnect PolygonConnect_8 [All vs IsNamedPolygon('C11_1') Or  IsNamedPolygon('Vin') Or  IsNamedPolygon('12V5') Or  IsNamedPolygon('Q3_3') Or  IsNamedPolygon('GND2') Or  IsNamedPolygon('GND2') Or  IsNamedPolygon('5V') Or  IsNamedPolygon('Q3_4') Or  IsNamedPolygon('12V5')] p8: connectstyle=Direct reliefconductorwidth=10 reliefentries=4 polygonreliefangle="90 Angle" airgapwidth=10
PolygonConnect PolygonConnect_7 [All vs IsNamedPolygon('GND2') Or  IsNamedPolygon('GND2') Or  IsNamedPolygon('5V') Or  IsNamedPolygon('12V5') Or  IsNamedPolygon('12V5') Or  IsNamedPolygon('C11_1')] p9: connectstyle=Direct reliefconductorwidth=10 reliefentries=4 polygonreliefangle="90 Angle" airgapwidth=10
PolygonConnect PolygonConnect_6 [All vs IsNamedPolygon('GND2') Or  IsNamedPolygon('SGND') Or  IsNamedPolygon('GND1') Or  IsNamedPolygon('C901_1') Or  IsNamedPolygon('SGND') Or  IsNamedPolygon('GND2') Or  IsNamedPolygon('GND1')] p10: connectstyle=Direct reliefconductorwidth=10 reliefentries=4 polygonreliefangle="90 Angle" airgapwidth=10
PolygonConnect PolygonConnect_5 [All vs IsNamedPolygon('GND1') Or  IsNamedPolygon('GND1')] p11: connectstyle=Direct reliefconductorwidth=10 reliefentries=4 polygonreliefangle="90 Angle" airgapwidth=10
PolygonConnect PolygonConnect_4 [All vs IsNamedPolygon('C21_1') Or  IsNamedPolygon('C5_1') Or  IsNamedPolygon('C12_2') Or  IsNamedPolygon('C2_2') Or  IsNamedPolygon('C13_1') Or  IsNamedPolygon('C28_1') Or  IsNamedPolygon('C6_1') Or  IsNamedPolygon('GND') Or  IsNamedPolygon('GND2') Or  IsNamedPolygon('C14_1') Or  IsNamedPolygon('C13_1') Or  IsNamedPolygon('Q1_3') Or  IsNamedPolygon('C14_1') Or  IsNamedPolygon('C5_1') Or  IsNamedPolygon('GND2') Or  IsNamedPolygon('C28_1') Or  IsNamedPolygon('D5_2') Or  IsNamedPolygon('D6_2') Or  IsNamedPolygon('D2_1') Or  IsNamedPolygon('C12_2') Or  IsNamedPolygon('D2_1') Or  IsNamedPolygon('C4_1') Or  IsNamedPolygon('C4_1') Or  IsNamedPolygon('C2_2') Or  IsNamedPolygon('GND') Or  IsNamedPolygon('C33_1') Or  IsNamedPolygon('C9_1')] p12: connectstyle=Direct reliefconductorwidth=10 reliefentries=4 polygonreliefangle="90 Angle" airgapwidth=10
PolygonConnect PolygonConnect_3 [All vs IsNamedPolygon('C28_1') Or  IsNamedPolygon('C12_2') Or  IsNamedPolygon('C28_1') Or  IsNamedPolygon('C9_1') Or  IsNamedPolygon('D5_2') Or  IsNamedPolygon('C12_2') Or  IsNamedPolygon('C2_2') Or  IsNamedPolygon('C14_1') Or  IsNamedPolygon('C4_1') Or  IsNamedPolygon('C14_1') Or  IsNamedPolygon('D6_2') Or  IsNamedPolygon('GND2') Or  IsNamedPolygon('Q1_3') Or  IsNamedPolygon('C5_1') Or  IsNamedPolygon('D2_1') Or  IsNamedPolygon('C4_1') Or  IsNamedPolygon('C13_1') Or  IsNamedPolygon('C5_1') Or  IsNamedPolygon('C13_1') Or  IsNamedPolygon('C33_1') Or  IsNamedPolygon('D2_1') Or  IsNamedPolygon('GND') Or  IsNamedPolygon('GND') Or  IsNamedPolygon('GND2') Or  IsNamedPolygon('C2_2') Or  IsNamedPolygon('C6_1') Or  IsNamedPolygon('C21_1')] p13: connectstyle=Direct reliefconductorwidth=10 reliefentries=4 polygonreliefangle="90 Angle" airgapwidth=10
PolygonConnect PolygonConnect_2 [All vs IsNamedPolygon('C21_1') Or  IsNamedPolygon('C4_1') Or  IsNamedPolygon('D5_2') Or  IsNamedPolygon('C5_1') Or  IsNamedPolygon('C14_1') Or  IsNamedPolygon('C13_1') Or  IsNamedPolygon('C4_1') Or  IsNamedPolygon('C33_1') Or  IsNamedPolygon('C12_2') Or  IsNamedPolygon('D2_1') Or  IsNamedPolygon('C2_2') Or  IsNamedPolygon('C28_1') Or  IsNamedPolygon('C12_2') Or  IsNamedPolygon('D2_1') Or  IsNamedPolygon('C5_1') Or  IsNamedPolygon('Q1_3') Or  IsNamedPolygon('GND') Or  IsNamedPolygon('D6_2') Or  IsNamedPolygon('C6_1') Or  IsNamedPolygon('C2_2') Or  IsNamedPolygon('C14_1') Or  IsNamedPolygon('C28_1') Or  IsNamedPolygon('C13_1') Or  IsNamedPolygon('C9_1') Or  IsNamedPolygon('GND')] p14: connectstyle=Direct reliefconductorwidth=10 reliefentries=4 polygonreliefangle="90 Angle" airgapwidth=10
PolygonConnect PolygonConnect_1 [All vs IsNamedPolygon('C28_1') Or  IsNamedPolygon('D5_2') Or  IsNamedPolygon('C5_1') Or  IsNamedPolygon('C5_1') Or  IsNamedPolygon('D2_1') Or  IsNamedPolygon('C21_1') Or  IsNamedPolygon('C9_1') Or  IsNamedPolygon('C4_1') Or  IsNamedPolygon('C14_1') Or  IsNamedPolygon('C28_1') Or  IsNamedPolygon('C6_1') Or  IsNamedPolygon('C12_2') Or  IsNamedPolygon('C33_1') Or  IsNamedPolygon('C4_1') Or  IsNamedPolygon('C13_1') Or  IsNamedPolygon('C12_2') Or  IsNamedPolygon('D6_2') Or  IsNamedPolygon('C2_2') Or  IsNamedPolygon('C14_1') Or  IsNamedPolygon('D2_1') Or  IsNamedPolygon('C2_2') Or  IsNamedPolygon('C13_1')] p15: connectstyle=Direct reliefconductorwidth=10 reliefentries=4 polygonreliefangle="90 Angle" airgapwidth=10
PolygonConnect [All] p16: connectstyle=Direct reliefconductorwidth=10 reliefentries=4 polygonreliefangle="90 Angle" airgapwidth=10
RoutingVias ThermalPadVias [IsVia and InAnyComponent] p1: holewidth=7.87 width=19.68 viastyle="Through Hole" minholewidth=7.87 minwidth=19.68 maxholewidth=12.99 maxwidth=23.62
RoutingVias [All] p2: holewidth=16 width=34 viastyle="Through Hole" minholewidth=7.87 minwidth=20 maxholewidth=40 maxwidth=65
SilkToBoardRegionClearance [Not ((IsComment or IsDesignator) And (Hide <> 'False')) and not InRegion(1000,500,4000,800)] p1:
SilkToSilkClearance SilkToSilkClearance_Pb-FreeLogo [(HasFootprint('Pb-Free_Overlay_Medium') OR HasFootprint('Pb-Free_Overlay_Small')) vs (HasFootprint('Pb-Free_Overlay_Medium') OR HasFootprint('Pb-Free_Overlay_Small'))] p1: silktosilkclearance=0
SilkToSilkClearance [All] p2: silktosilkclearance=4
SilkToSolderMaskClearance SilkToComponentPadClearance [IsPad and InAnycomponent] p1: minsilkscreentomaskgap=5 clearancetoexposedcopper=TRUE
SilkToSolderMaskClearance "Silk to Solder Mask Opening" [All] p2: minsilkscreentomaskgap=4 clearancetoexposedcopper=FALSE
SolderMaskExpansion [All] p1: expansion=1.97 istentingtop=FALSE
SupplyNets "Schematic Supply Nets_1" [InNet('GND')] p1: voltage=0.000
SupplyNets "Schematic Supply Nets_5" [InNet('3V3')] p2: voltage=0.000
SupplyNets "Schematic Supply Nets_4" [InNet('5V0')] p3: voltage=0.000
SupplyNets "Schematic Supply Nets_2" [InNet('AGND')] p4: voltage=0.000
SupplyNets "Schematic Supply Nets" [InNet('VBUS')] p5: voltage=0.000
Width [All] p1: maxlimit=100 minlimit=6 preferedwidth=10 checkconnectedcopper=TRUE
14 further rules are at their usual default settings.

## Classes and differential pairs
component class FiducialMark: FID1 FID2 FID3 FID4 FID5 FID6
component class SR161A_Hardware: !PCB FID1 FID2 FID3 FID4 FID5 FID6 H1 H2 H3 H4 Logo3 LOGO4 Logo5 Logo6 MP1 MP2 MP3 MP4 SH-JP1 SH-JP2 SH-JP3 SH-JP4 SH-JP5 SH-JP6 SH-JP7 SH-JP8 ZZ2 ZZ3 ZZ4 ZZ5 ZZ6 ZZ7 ZZ8 ZZ9 ZZ10 ZZ11
component class AssemblyNote: ZZ2 ZZ3 ZZ4 ZZ5 ZZ6 ZZ7 ZZ8 ZZ9 ZZ10 ZZ11
component class Header: J3 J4 J9 J11 JP1 JP2 JP3 JP4 JP5 JP6 JP7 JP8

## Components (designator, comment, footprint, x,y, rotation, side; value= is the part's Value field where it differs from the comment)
C1 "C3225X7R2A106K250AC" FP-C3225X7R2A106K250AC_1210-MFG 853.69,1039.81 r180 top value=10µF
C2 "GRM155R62A104ME14D" FP-GRM155R62A104ME14D_0402-S 1433.47,2363.18 r270 top value=100nF
C3 "C3225X7R2A106K250AC" FP-C3225X7R2A106K250AC_1210-MFG 1531.52,1675.76 r0 top value=10µF
C4 "GRM155R62A104ME14D" FP-GRM155R62A104ME14D_0402-S 746.81,1778.57 r0 top value=100nF
C5 "C3225X7R2A106K250AC" FP-C3225X7R2A106K250AC_1210-MFG 1734.05,1675.76 r0 top value=10µF
C6 "GRM155R62A104ME14D" FP-GRM155R62A104ME14D_0402-S 894.63,1929.94 r180 top value=100nF
C7 "A768KE276M1JLAE054" FP-A768KE276M1JLAE054_SMT_CAP_8MM3_8MM3-0 2094.18,1608.9 r90 top value=27µF
C8 "GRM155R62A104ME14D" FP-GRM155R62A104ME14D_0402-S 2287.1,847.12 r0 top value=100nF
C9 "C3225X7R2A106K250AC" FP-C3225X7R2A106K250AC_1210-MFG 1260.05,2346.17 r180 top value=10µF
C10 "GRM155R62A104ME14D" FP-GRM155R62A104ME14D_0402-S 1733.93,1852.23 r180 top value=100nF
C11 "GRM155R62A104ME14D" FP-GRM155R62A104ME14D_0402-S 863.67,852.61 r0 top value=100nF
C12 "GRM155R62A104ME14D" FP-GRM155R62A104ME14D_0402-S 1282.57,2157.68 r90 top value=100nF
C13 "GRM155R62A104ME14D" FP-GRM155R62A104ME14D_0402-S 1733.93,1883.54 r180 top value=100nF
C14 "04025A101FAT2A" 0402S 1635.97,2364.45 r90 top value=100pF
C15 "GRM155R62A104ME14D" FP-GRM155R62A104ME14D_0402-S 1651.05,2011.26 r180 top value=100nF
C16 "GRM155R62A104ME14D" FP-GRM155R62A104ME14D_0402-S 1591.32,2365.5 r90 top value=100nF
C17 "A768KE276M1JLAE054" FP-A768KE276M1JLAE054_SMT_CAP_8MM3_8MM3-0 868.31,2211.1 r90 top value=27µF
C18 "GRM155R62A104ME14D" FP-GRM155R62A104ME14D_0402-S 1732.15,2381.66 r0 top value=100nF
C19 "C3225X7R2A106K250AC" FP-C3225X7R2A106K250AC_1210-MFG 1260.05,2347.5 r180 bottom value=10µF
C20 "C3225X7R2A106K250AC" FP-C3225X7R2A106K250AC_1210-MFG 1260.75,2237.32 r180 top value=10µF
C21 "C3225X7R2A106K250AC" FP-C3225X7R2A106K250AC_1210-MFG 1813.16,1820.35 r270 top value=10µF
C22 "GRM1555C1H681JA01D" 0402S 1618.05,1914.54 r180 top value=680pF
C23 "GRM1555C1H821JA01D" 0402S 1486.08,1916.01 r0 top value=820pF
C24 "GRM155R62A104ME14D" FP-GRM155R62A104ME14D_0402-S 1733.93,1820.52 r180 top value=100nF
C25 "GRM1555C1H680JA01D" 0402S 1434.64,2288.19 r270 top value=68pF
C26 "GRT188R61A226ME13D" 0603S 1827.16,2008.7 r90 top value=22µF
C27 "GRT188R61A226ME13D" 0603S 1471.87,2100.07 r270 top value=22µF
C28 "GRM155R62A104ME14D" FP-GRM155R62A104ME14D_0402-S 1764.62,2010.83 r0 top value=100nF
C29 "GRM155R62A104ME14D" FP-GRM155R62A104ME14D_0402-S 1710.99,2011.07 r0 top value=100nF
C30 "GRM2195C2A681JA01D" 0805_HV 1324.91,2080.03 r0 bottom value=680pF
C31 "GRM188R72A104KA35D" 0603S 1471.26,2212.29 r270 top value=0.1uF
C32 "GRM2195C2A102JA01D" 0805_HV 1364.78,1780.18 r270 bottom value=1000pF
C33 "GRM188R72A104KA35D" 0603S 1564.47,2003.25 r180 top value=0.1uF
C34 "GRM1555C1H151JA01D" 0402S 1777.94,2364.12 r90 top value=150pF
C35 "GRM1555C1H560JA01D" 0402S 1801.61,2283.12 r0 bottom value=56pF
C36 "GRM155R71H822KA88D" 0402S 1847.6,2363.45 r270 top value=8200pF
C37 "GRM155R71C223KA01D" 0402S 1828.7,2073.13 r0 top value=0.022uF
C38 "GRM1555C1H681JA01D" 0402S 1381.16,2090.13 r270 top value=680pF
C39 "GRM1555C1H821JA01D" 0402S 1350.74,1939.07 r270 top value=820pF
C40 "C3225X7R2A106K250AC" FP-C3225X7R2A106K250AC_1210-MFG 2030.36,1749.11 r0 bottom value=10µF
C41 "GRM155R62A104ME14D" FP-GRM155R62A104ME14D_0402-S 1313.58,2157.68 r90 top value=100nF
C42 "GRM155R62A104ME14D" FP-GRM155R62A104ME14D_0402-S 1242.75,2161.98 r0 top value=100nF
C43 "GRM21BR72A474KA73L" 0805L 852.32,937.06 r0 top value=0.47uF
C44 "C3225X7R2A106K250AC" FP-C3225X7R2A106K250AC_1210-MFG 700,1563.26 r180 top value=10µF
C45 "GRM21BR72A474KA73L" 0805L 696.46,1445.51 r0 top value=0.47uF
D1 "MMSZ4684T1G" SOD-123 2014.64,2755.77 r0 bottom value=3.3V
D2 "BAS70-04-E3-18" FP-BAS70-04-E3-18_SOT23-3-MFG 830.72,1864.97 r90 top
D3 "PMEG6010CEGWJ" SOD-123 1185.82,1553 r180 top value=60V
D4 "PMEG6010CEJ,115" SOD-323F 1507.71,2143.9 r270 bottom value=60V
D5 "PMEG6010CEJ,115" SOD-323F 1530.65,2010.13 r180 bottom value=60V
D6 "PMEG6010CEGWJ" SOD-123 1091.47,2005.14 r90 top value=60V
FID1 "Fiducial" Fiducial10-20 3025,390 r0 top
FID2 "Fiducial" Fiducial10-20 3025,3350 r0 top
FID3 "Fiducial" Fiducial10-20 125,3350 r0 top
FID4 "Fiducial" Fiducial10-20 3025,390 r180 bottom
FID5 "Fiducial" Fiducial10-20 3025,3350 r180 bottom
FID6 "Fiducial" Fiducial10-20 125,3350 r180 bottom
H1 "PMSSS 440 0025 PH" B_F_PMSSS4400025PH 165,165 r0 top
H2 "PMSSS 440 0025 PH" B_F_PMSSS4400025PH 2985,165 r0 top
H3 "PMSSS 440 0025 PH" B_F_PMSSS4400025PH 2985,3575 r0 top
H4 "PMSSS 440 0025 PH" B_F_PMSSS4400025PH 165,3574 r0 top
J1 "108-0740-001" Johnson_108-0740-001 2638,364.6 r90 top
J2 "108-0740-001" Johnson_108-0740-001 512.16,366.19 r270 top
J3 "61300611121" WURTH_61300611121 863,756.82 r0 top
J4 "61300611121" WURTH_61300611121 2288,756.82 r180 top
J5 "108-0740-001" Johnson_108-0740-001 1142.16,366.19 r270 top
J6 "108-0740-001" Johnson_108-0740-001 2008,364.6 r90 top
J7 "SSQ-110-03-T-D" Samtec_SSQ-110-03-x-D 1599.03,2911.43 r180 bottom
J8 "SSQ-110-03-T-D" Samtec_SSQ-110-03-x-D 1599.03,1211.43 r180 bottom
J9 "61300211121" WURTH_61300211121 693,3440 r270 top
J10 "N2510-6002-RB" CONN_2510-6002 1213,3502.5 r0 top
J11 "61300211121" WURTH_61300211121 1733,3440 r270 top
J12 "RSP-122811-01" FP-RSP-122811-01_CONN_UFL-MFG 1012.73,1795.91 r90 top
J13 "RSP-122811-01" FP-RSP-122811-01_CONN_UFL-MFG 1258.5,1410.8 r180 top
JP1 "61300211121" WURTH_61300211121 1883,3440 r270 top
JP2 "61300511121" Wurth_61300511121 1605,2505 r0 top
JP3 "61300311121" WURTH_61300311121 2793,3490 r90 top
JP4 "61300311121" WURTH_61300311121 2603,3490 r90 top
JP5 "61300311121" WURTH_61300311121 2413,3490 r90 top
JP6 "61300211121" WURTH_61300211121 2033,3440 r270 top
JP7 "61300311121" WURTH_61300311121 543,3490 r90 top
JP8 "61300311121" WURTH_61300311121 2223,3490 r90 top
L1 "744393465033" FP-744393465033_SMT_IND_6MM4_6MM6-MFG 1274,1726 r270 top value=3.3uH
L2 "7443845030022" FP-7443845030022_SMT_IND_5MM4_5MM4-MFG 531.12,1140 r90 top value=2.2uH
Logo3 "FCC disclaimer" FCC_disclaimer 3086.05,2035.71 r90 top
LOGO4 "WEEE logo" WEEE_Minimum 2981.35,1156.09 r0 top (schematic designator Logo4)
Logo5 "CAUTION HOT SURFACE" IEC_HotSurface_Small 2107.76,1967.56 r0 top
Logo6 "CAUTION.  READ USER GUIDE BEFORE USE" IEC_Caution_Small 2840,1426.75 r90 top
MP1 "1902D_Ndrill" FP-1902D_Ndrill_HEX_STANDOFF-MFG 165,165 r180 bottom
MP2 "1902D_Ndrill" FP-1902D_Ndrill_HEX_STANDOFF-MFG 2985,165 r180 bottom
MP3 "1902D_Ndrill" FP-1902D_Ndrill_HEX_STANDOFF-MFG 2985,3575 r180 bottom
MP4 "1902D_Ndrill" FP-1902D_Ndrill_HEX_STANDOFF-MFG 165,3575 r180 bottom
NT3 "Net-Tie" Net-Tie_10mil 1618.47,2286.19 r90 top net-tie
Q1 "IAUZN04S7L046ATMA1" FP-NVTFS5C673NLTAG_WDFN8-Recommended_Land_Pattern 1243.83,2067.49 r90 top
Q2 "IAUZN04S7L046ATMA1" FP-NVTFS5C673NLTAG_WDFN8-Recommended_Land_Pattern 1261.36,1921.2 r90 top
Q3 "IAUZN04S7L046ATMA1" FP-NVTFS5C673NLTAG_WDFN8-Recommended_Land_Pattern 1473.44,1817.09 r180 top
Q4 "IAUZN04S7L046ATMA1" FP-NVTFS5C673NLTAG_WDFN8-Recommended_Land_Pattern 1632.53,1809.74 r270 top
Q5 "CSD18540Q5B" DNK0008A 546.54,1838.04 r90 top value=60V
R1 "KRL2012E-C-R010-F-T05" FP-KRL2012E-C-R010-F-T05_0508-MFG 587.95,2053.29 r90 top value=10m
R2 "ERJ-2GE0R00X" FP-ERJ-2GE0R00X_0402-MFG 1560.78,2362.57 r270 top value=0
R3 "KRL2012E-C-R010-F-T05" FP-KRL2012E-C-R010-F-T05_0508-MFG 1873,1675.58 r0 top value=10m
R4 "KRL2012E-M-R004-F-T5" FP-KRL2012E-M-R004-F-T5_2012-MFG 1422.4,1976.54 r270 top value=4m
R5 "ERJ-2GE0R00X" FP-ERJ-2GE0R00X_0402-MFG 1412.03,2349.49 r0 bottom value=0
R6 "RMCF0603ZT0R00" 0603S 2276.88,1979.63 r0 bottom value=0
R7 "ERJ-2GE0R00X" FP-ERJ-2GE0R00X_0402-MFG 1640.03,1988.73 r270 bottom value=0
R8 "CRCW040210R0FKED" 0402S 1525.36,2433.72 r0 bottom value=10.0
R9 "ERJ-2GE0R00X" FP-ERJ-2GE0R00X_0402-MFG 1587.91,2361.64 r90 bottom value=0
R10 "ERJ-2GE0R00X" FP-ERJ-2GE0R00X_0402-MFG 1637.55,2309.05 r0 bottom value=0
R11 "ERJ-2GE0R00X" FP-ERJ-2GE0R00X_0402-MFG 1412.03,2381.01 r0 bottom value=0
R12 "RC0402FR-0782KL" 0402S 1491.02,2364.12 r270 top value=82.0k
R13 "ERJ-2GE0R00X" FP-ERJ-2GE0R00X_0402-MFG 1345.59,2129.66 r90 top value=0
R14 "ERJ-2GE0R00X" FP-ERJ-2GE0R00X_0402-MFG 1386.53,2344.28 r180 top value=0
R15 "ERJ-2GE0R00X" FP-ERJ-2GE0R00X_0402-MFG 1386.06,2381.62 r180 top value=0
R16 "RMCF0603ZT0R00" 0603S 1801.76,2375.14 r180 bottom value=0
R17 "CRCW040210R0FKED" 0402S 1383.57,2266 r180 top value=10.0
R18 "CRCW040210R0FKED" 0402S 1383.24,2308.19 r180 top value=10.0
R19 "CRCW04022K67FKED" 0402S 1528.4,2364.07 r90 top value=2.67k
R20 "ERJ-2GE0R00X" FP-ERJ-2GE0R00X_0402-MFG 1563.05,1947 r90 top value=0
R21 "CRCW040275K0FKED" 0402S 1640.03,1978.74 r180 top value=75.0k
R22 "CRCW040212K7FKED" 0402S 1702.99,1978.97 r180 top value=12.7k
R23 "CRCW12063R00JNEA" 1206 1342.15,2206.39 r90 bottom value=3.0
R24 "ERJ-2GE0R00X" FP-ERJ-2GE0R00X_0402-MFG 1829.46,2107.13 r0 top value=0
R25 "MCS0402MD1002BE100" 0402S 1801.76,2242.01 r0 bottom value=10.0k
R26 "CRCW12063R00JNEA" 1206 1443.03,1666.87 r0 bottom value=3.0
R27 "RMCF0603ZT0R00" 0603S 1821.35,2090.12 r0 bottom value=0
R28 "CRCW04023R00JNED" 0402S 1423.59,2120.72 r270 top value=3.0
R29 "CRCW04028K66FKED" 0402S 1813.66,2363.28 r270 top value=8.66k
R30 "CRCW040240K2FKED" 0402S 1833.99,2324.38 r180 bottom value=40.2k
R31 "CRCW040215K4FKED" 0402S 1830.67,2310.21 r180 top value=15.4k
R32 "CRCW04023R00JNED" 0402S 1484.88,1967.44 r270 top value=3.0
R33 "RMCF0603ZT0R00" 0603S 1821.35,2035.21 r180 bottom value=0
R34 "CRCW04025K11FKED" 0402S 751.96,1737.49 r0 top value=5.11k
R35 "ERJ-2GE0R00X" FP-ERJ-2GE0R00X_0402-MFG 1700,2020 r270 bottom value=0
R36 "ERJ-2GE0R00X" FP-ERJ-2GE0R00X_0402-MFG 1831.08,2277.66 r180 top value=0
R37 "CRCW04022K74FKED" 0402S 1817,2221.96 r90 top value=2.74k
R38 "ERJ-2GE0R00X" FP-ERJ-2GE0R00X_0402-MFG 1849.47,2218.61 r270 top value=0
R39 "RC0603FR-072KL" 0603S 1488.82,3406.74 r270 bottom value=2.00k
R40 "RC0603FR-072KL" 0603S 1548.82,3406.74 r270 bottom value=2.00k
R41 "RMCF0603ZT0R00" 0603S 1175.98,2761.76 r180 bottom value=0
R42 "RMCF0603ZT0R00" 0603S 1317.59,2763.85 r0 bottom value=0
R43 "RMCF0603ZT0R00" 0603S 1816.48,1943.31 r180 bottom value=0
R44 "RC0603FR-072KL" 0603S 1700,1930 r270 bottom value=2.00k
R45 "RC0603FR-0771K5L" 0603S 1815.07,2761.65 r180 bottom value=71.5k
R46 "RC0603FR-0771K5L" 0603S 1492.51,2761.76 r0 bottom value=71.5k
R47 "RC0603FR-074K7L" 0603S 1708.93,2761.65 r0 bottom value=4.70k
R48 "RC0603FR-074K7L" 0603S 1598.34,2761.76 r180 bottom value=4.70k
R49 "RMCF0603ZT0R00" 0603S 1749.62,2083.15 r270 bottom value=0
R50 "RMCF0603ZT0R00" 0603S 2276.88,2091.78 r0 bottom value=0
R51 "RMCF0603ZT0R00" 0603S 2276.88,2035.71 r0 bottom value=0
R52 "ERJ-2GE0R00X" FP-ERJ-2GE0R00X_0402-IPC_C 1679.48,2381.58 r180 top value=0
R53 "RC0603FR-0718KL" 0603S 443.23,3300.37 r180 bottom value=18.0k
R54 "RT0603BRD0710KL" 0603S 2041.62,2090.99 r90 bottom value=10.0k
R55 "RMCF0603ZT0R00" 0603S 1671.34,2375.26 r0 bottom value=0
SH-JP1 "M7582-05" Harwin_M7582-05 1883,3440 r90 top
SH-JP2 "M7582-05" Harwin_M7582-05 1755,2505 r180 top
SH-JP3 "M7582-05" Harwin_M7582-05 2793,3440 r90 top
SH-JP4 "M7582-05" Harwin_M7582-05 2603,3540 r90 top
SH-JP5 "M7582-05" Harwin_M7582-05 2413,3540 r90 top
SH-JP6 "M7582-05" Harwin_M7582-05 2033,3440 r90 top
SH-JP7 "M7582-05" Harwin_M7582-05 543,3440 r90 top
SH-JP8 "M7582-05" Harwin_M7582-05 2223,3440 r90 top
TP1 "5003" Keystone5003 396.09,2030.45 r0 top
TP2 "5003" Keystone5003 1860.73,1452.1 r90 top
TP3 "5000" Keystone5000 363,756.82 r90 top
TP4 "5001" Keystone5001 1987.84,2519.28 r180 top
TP5 "5003" Keystone5003 396.09,2333.54 r0 top
TP6 "5003" Keystone5003 1726.13,1452.1 r90 top
TP7 "5001" Keystone5001 2124.72,2447.28 r0 top
TP8 "5001" Keystone5001 1363,756.82 r270 top
TP9 "5004" Keystone5004 2124.72,2303.28 r0 top
TP10 "5004" Keystone5004 2124.72,2159.28 r0 top
TP11 "5004" Keystone5004 1473.44,1543.96 r90 top
TP12 "5004" Keystone5004 1987.84,2375.28 r180 top
TP13 "5004" Keystone5004 1987.84,2231.28 r0 top
TP14 "5000" Keystone5000 2788,756.82 r90 top
TP15 "5001" Keystone5001 1788,756.82 r90 top
U1 "LM34938QRHARQ1" RHA0040P-MFG 1648,2183.76 r180 top
ZZ2 "These assemblies are ESD sensitive, ESD precautions shall be observed." AssemblyNote 185,3840 r0 top
ZZ3 "These assemblies must be clean and free from flux and all contaminants. Use of no clean flux is not acceptable." AssemblyNote 185,3930 r0 top
ZZ4 "These assemblies must comply with workmanship standards IPC-A-610 Class 2, unless otherwise specified." AssemblyNote 185,4040 r0 top
ZZ5 "Install Shunt Jumper SH-JP1 onto JP1" AssemblyNote 185,4140 r0 top
ZZ6 "Install Shunt Jumper SH-JP3 onto JP3 pins 1-2" AssemblyNote 185,4240 r0 top
ZZ7 "Install Shunt Jumper SH-JP4 onto JP4 pins 2-3" AssemblyNote 185,4340 r0 top
ZZ8 "Install Shunt Jumper SH-JP5 onto JP5 pins 2-3" AssemblyNote 185,4440 r0 top
ZZ9 "Install Shunt Jumper SH-JP6 onto JP6" AssemblyNote 185,4540 r0 top
ZZ10 "Install Shunt Jumper SH-JP8 onto JP8" AssemblyNote 185,4640 r0 top
ZZ11 "Install Shunt Jumper SH-JP9 onto JP9 pins 1-2" AssemblyNote 185,4740 r0 top

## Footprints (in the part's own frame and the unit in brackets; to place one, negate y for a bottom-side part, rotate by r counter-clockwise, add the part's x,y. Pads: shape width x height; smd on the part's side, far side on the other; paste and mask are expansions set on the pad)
0402S [mil] "Based on C0402S footprint from PADS legacy"
  rect 15x24 smd: 1(-20,0) 2(20,0)
  body extent -22,-12 22,12, height 24
0603S [mil]
  rect 20x35 smd: 1(-30,0) 2(30,0)
  body extent -34,-19 34,19, height 39
0805_HV [mil] "0805 with 30mil clearance between pads"
  rect 50x63 smd: 1(-40,0) 2(40,0)
  body extent -43,-29 43,29, height 57
0805L [mm] "0805 from SM-752 data"
  rect 1.1x1.4 smd: 1(-0.75,0) 2(0.75,0)
  body extent -1.1,-0.72 1.1,0.72, height 1.45
1206 [mm] "1206 from SM-752 data"
  rect 1.3x1.85 smd: 1(-1.45,0) 2(1.45,0)
  body extent -1.7,-0.9 1.7,0.9, height 1.35
AssemblyNote [mil] "Assembly Note"
B_F_PMSSS4400025PH [mil] "MACHINE SCREW PAN PHILLIPS 4-40"
  round 230 hole 125: 1(0,0)
  body extent -109,-109 110,110, height 79
CONN_2510-6002 [mm] "3M 2500 series TS-0770-L December 15, 2011"
  rect 1.65x1.65 hole 1.016 mask+0: 1(-5.08,-1.27)
  round 1.65 hole 1.016 mask+0: 2(-5.08,1.27) 3(-2.54,-1.27) 4(-2.54,1.27) 5(0,-1.27) 6(0,1.27) 7(2.54,-1.27) 8(2.54,1.27) 9(5.08,-1.27) 10(5.08,1.27)
  silkscreen extent -10.01,-4.17 10.01,4.47, body extent -10.01,-4.11 10.01,4.52, height 9.92
DNK0008A [mm] "SON, 8-Leads, Body 5x6mm"
  rrect39% 0.86x0.51 smd paste-0.05 mask-0.05: 1(-2.82,1.905) 2(-2.82,0.635) 3(-2.82,-0.635) 4(-2.82,-1.905) 5(2.82,-1.905) 6(2.82,-0.635) 7(2.82,0.635) 8(2.82,1.905)
  rrect40% 0.25x0.555 on Top Solder: 9(-0.83,2.372) 9(-0.83,-2.372)
  rrect40% 0.25x0.555 on Top Paste: 9(-0.83,2.372) 9(-0.83,-2.372)
  rrect11% 0.95x1.13 on Top Paste: 9(-0.535,1.33) 9(-0.535,0) 9(-0.535,-1.33) 9(0.615,1.33) 9(0.615,0) 9(0.615,-1.33) 9(1.765,-1.33) 9(1.765,0) 9(1.765,1.33)
  rrect3% 3.58x4 on Top Solder: 9(0.75,0)
  rrect5% 4.34x5.4 smd paste-3 mask-3: 9(1.08,0)
  body extent -3.05,-2.55 3.05,2.55, height 1.06
FCC_disclaimer [mil]
Fiducial10-20 [mm]
  round 1 smd mask+0.5: 1(0,0)
  Top Layer keep-out circle w1.178: c0,0 r0.5
FP-1902D_Ndrill_HEX_STANDOFF-MFG [mil]
  body extent -144,-125 144,125, height 765
FP-744393465033_SMT_IND_6MM4_6MM6-MFG [mm] "Recommended Land Pattern"
  rrect7% 1.45x5.5 smd paste+0 mask+0: 1(-2,0) 2(2,0)
  body extent -3.2,-3.3 3.2,3.3, height 6.1
FP-7443845030022_SMT_IND_5MM4_5MM4-MFG [mm] "Recommended Land Pattern"
  rrect6% 1.7x5.6 smd paste+0 mask+0: 1(-1.95,0) 2(1.95,0)
  body extent -2.7,-2.7 2.7,2.7, height 3.1
FP-A768KE276M1JLAE054_SMT_CAP_8MM3_8MM3-0 [mm]
  rrect5% 4.2x2.2 smd paste+0 mask+0: 1(-3.65,0) 2(3.65,0)
  silkscreen extent -4.25,-4.25 4.25,4.25, body extent -6,-4.5 6,4.5, height 0.25
FP-BAS70-04-E3-18_SOT23-3-MFG [mm]
  rrect14% 0.9x0.7 smd paste+0 mask+0: 1(-1,0.95) 2(-1,-0.95) 3(1,0)
  silkscreen extent -0.71,-1.55 0.71,1.55, body extent -1.55,-1.65 1.55,1.65, height 0.25
FP-C3225X7R2A106K250AC_1210-MFG [mm]
  rrect9% 1.1x2.2 smd paste+0 mask+0: 1(-1.65,0) 2(1.65,0)
  silkscreen extent -0.72,-1.43 0.72,1.43, body extent -2.3,-1.53 2.3,1.53, height 0.25
FP-ERJ-2GE0R00X_0402-IPC_C [mil]
  rrect21% 18.43x18.6 smd paste+0 mask+0: 1(-15.83,0) 2(15.83,0)
  body extent -29,-15 29,15, height 10
FP-ERJ-2GE0R00X_0402-MFG [mm]
  rrect21% 0.475x0.5 smd paste+0 mask+0: 1(-0.512,0) 2(0.513,0)
  body extent -0.85,-0.38 0.85,0.38, height 0.25
FP-GRM155R62A104ME14D_0402-S [mm]
  rrect25% 0.4x0.5 smd paste+0 mask+0: 1(-0.4,0) 2(0.4,0)
  body extent -0.7,-0.37 0.7,0.38, height 0.25
FP-KRL2012E-C-R010-F-T05_0508-MFG [mm]
  rrect14% 0.7x2.2 smd paste+0 mask+0: 1(-0.65,0) 2(0.65,0)
  silkscreen extent -0.72,-1.5 0.72,1.5, body extent -1.1,-1.2 1.1,1.2, height 0.25
FP-KRL2012E-M-R004-F-T5_2012-MFG [mm]
  rrect14% 0.7x2.2 smd paste+0 mask+0: 1(-0.65,0) 2(0.65,0)
  body extent -1.1,-1.2 1.1,1.2, height 0.25
FP-NVTFS5C673NLTAG_WDFN8-Recommended_Land_Pattern [mm]
  rect 0.42x0.66 smd paste+0 mask+0: 1(-0.975,-1.47) 2(-0.325,-1.47) 3(0.325,-1.47) 4(0.975,-1.47)
  rect 0.545x0.57 smd paste+0 mask+0: 5-6-7-8(-1.458,-0.035) 5-6-7-8(1.458,-0.035)
  rect 0.42x0.47 smd paste+0 mask+0: 5-6-7-8(-0.975,1.565) 5-6-7-8(-0.325,1.565) 5-6-7-8(0.325,1.565) 5-6-7-8(0.975,1.565)
  rect 2.37x1.83 smd paste+0 mask+0: 5-6-7-8(0,0.415)
  body extent -1.83,-1.9 1.83,1.9, height 0.25
FP-RSP-122811-01_CONN_UFL-MFG [mm] "Recommended Land Pattern"
  rrect10% 1x1.05 smd paste+0 mask+0: 1(0,-1.525)
  rrect10% 1.05x2.2 smd paste+0 mask+0: 2(-1.475,0) 3(1.475,0)
  silkscreen extent -1.35,-2.75 1.35,1.6, body extent -2.1,-2.15 2.1,1.7, height 0.25
Harwin_M7582-05 [mil] "Single Operation 2.54mm Pitch Open Top Jumper Socket"
  body extent -98,-47 98,47, height 236
IEC_Caution_Small [mil]
  silkscreen extent -107,-93 107,92
IEC_HotSurface_Small [mil]
  silkscreen extent -107,-93 107,92
Johnson_108-0740-001 [mm] "Banana Jack Uninsulated Standard Type"
  round 12 hole 6.858: 1(0,0)
  body extent -4.77,-5.43 4.75,5.57, height 2.39
Keystone5000 [mil] "For Keystone 500x miniature loop terminals"
  round 80 hole 40: 1(0,0)
  silkscreen extent -52,-52 52,52, body extent -49,-49 49,49, height 182
Keystone5001 [mil] "For Keystone 500x miniature loop terminals"
  round 80 hole 40: 1(0,0)
  silkscreen extent -52,-52 52,52, body extent -49,-49 49,49, height 182
Keystone5003 [mil] "For Keystone 500x miniature loop terminals"
  round 80 hole 40: 1(0,0)
  silkscreen extent -52,-52 52,52, body extent -49,-49 49,49, height 182
Keystone5004 [mil] "For Keystone 500x miniature loop terminals"
  round 80 hole 40: 1(0,0)
  silkscreen extent -52,-52 52,52, body extent -49,-49 49,49, height 182
Net-Tie_10mil [mil] "10mil net tie, no solder mask opening, no solder paste"
  rect 10x10 smd paste-5 mask-5: 1(-10,0) 2(10,0)
  Top Layer region: -6,5 6,5 6,-5 -6,-5
RHA0040P-MFG [mm] "Recommended Land Pattern"
  rrect40% 0.6x0.25 smd paste+0 mask+0: 1(-2.9,2.25) 2(-2.9,1.75) 3(-2.9,1.25) 4(-2.9,0.75) 5(-2.9,0.25) 6(-2.9,-0.25) 7(-2.9,-0.75) 8(-2.9,-1.25) 9(-2.9,-1.75) 10(-2.9,-2.25) 21(2.9,-2.25) 22(2.9,-1.75) 23(2.9,-1.25) 24(2.9,-0.75) 25(2.9,-0.25) 26(2.9,0.25) 27(2.9,0.75) 28(2.9,1.25) 29(2.9,1.75) 30(2.9,2.25)
  rrect40% 0.25x0.6 smd paste+0 mask+0: 11(-2.25,-2.9) 12(-1.75,-2.9) 13(-1.25,-2.9) 14(-0.75,-2.9) 15(-0.25,-2.9) 16(0.25,-2.9) 17(0.75,-2.9) 18(1.25,-2.9) 19(1.75,-2.9) 20(2.25,-2.9) 31(2.25,2.9) 32(1.75,2.9) 33(1.25,2.9) 34(0.75,2.9) 35(0.25,2.9) 36(-0.25,2.9) 37(-0.75,2.9) 38(-1.25,2.9) 39(-1.75,2.9) 40(-2.25,2.9)
  rrect3% 3.3x3.3 smd paste-1000 mask+0: 41(0,0)
  silkscreen extent -3.49,-3.05 3.05,3.05, body extent -3,-3 3,3, height 1
Samtec_SSQ-110-03-x-D [mm] "Receptacle, 2.54mm, 10x2, TH"
  rect 1.55x1.55 hole 1.02: 1(-11.43,1.27)
  round 1.55 hole 1.02: 2(-11.43,-1.27) 3(-8.89,1.27) 4(-8.89,-1.27) 5(-6.35,1.27) 6(-6.35,-1.27) 7(-3.81,1.27) 8(-3.81,-1.27) 9(-1.27,1.27) 10(-1.27,-1.27) 11(1.27,1.27) 12(1.27,-1.27) 13(3.81,1.27) 14(3.81,-1.27) 15(6.35,1.27) 16(6.35,-1.27) 17(8.89,1.27) 18(8.89,-1.27) 19(11.43,1.27) 20(11.43,-1.27)
  silkscreen extent -12.95,-2.48 12.95,3, body extent -12.95,-2.48 12.95,2.48, height 8.51
SOD-123 [mm] "On Semi recommended land pattern"
  rect 0.915x1.22 smd: 1(-1.637,0) 2(1.637,0)
  silkscreen extent -2.74,-1.17 2.03,1.17, body extent -1.93,-0.9 1.93,0.9, height 1.35
SOD-323F [mm] "NXP recommended land pattern"
  rect 0.6x0.6 smd paste-0.05: 1(-1.1,0) 2(1.1,0)
  silkscreen extent -2.06,-0.86 1.53,0.86, body extent -1.35,-0.67 1.35,0.67, height 0.79
WEEE_Minimum [mil] "WEEElie bin"
  silkscreen extent -95,-172 99,104
WURTH_61300211121 [mm] "Header, 2.54mm, 2x1, TH"
  rrect50% 1.65x1.65 hole 1.15: 1(-1.27,0)
  round 1.65 hole 1.15: 2(1.27,0)
  body extent -2.54,-1.27 2.54,1.27, height 8.54
WURTH_61300311121 [mm] "Header, 2.54mm, 3x1, TH"
  rrect50% 1.65x1.65 hole 1.15: 1(-2.54,0)
  round 1.65 hole 1.15: 2(0,0) 3(2.54,0)
  body extent -3.81,-1.27 3.81,1.27, height 8.54
Wurth_61300511121 [mm] "Header, 2.54mm, 5x1, TH"
  rrect50% 1.65x1.65 hole 1.1: 1(-5.08,0)
  round 1.65 hole 1.1: 2(-2.54,0) 3(0,0) 4(2.54,0) 5(5.08,0)
  body extent -6.35,-1.27 6.35,1.27, height 8.54
WURTH_61300611121 [mm] "Header, 2.54mm, 6x1, TH"
  rrect50% 1.65x1.65 hole 1.15: 1(-6.35,0)
  round 1.65 hole 1.15: 2(-3.81,0) 3(-1.27,0) 4(1.27,0) 5(3.81,0) 6(6.35,0)
  body extent -7.62,-1.27 7.62,1.27, height 8.54

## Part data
C1 C3 C5 C9 C19 C20 C21 C40 C44: library part CMP-0096021-1, "10 µF ±10% 100V Ceramic Capacitor X7R 1210 (3225 Metric)", Digikey Part Number=445-C3225X7R2A106K250ACCT-ND, Manufacturer=TDK, Mouser Part Number=810-C3225X7R2A106K25, Operating Temperature Range="-55°C to +125°C", TempCo=15%, Temperature Characteristic=X7R, Tolerance_%=10%, ValueDisplayed=10uF
C2 C4 C6 C8 C10 C11 C12 C13 C15 C16 C18 C24 C28 C29 C41 C42: library part CMP-0093748-2, "Chip Multilayer Ceramic Capacitors for General Purpose, 0402, 0.10uF, X5R, 15%, 20%, 100V", Manufacturer=Murata, Operating Temperature Range="-55°C to +85°C", TempCo=15%, Temperature Characteristic=X5R, Tolerance_%=20%, ValueDisplayed=0.10uF
C7 C17: library part CMP-0097690-1, "Cap Aluminum Polymer 27uF 63V 20% Solder Cylindrical 54m Ohm 1175mA 2000 hr 125°C T/R", Digikey Part Number=399-A768KE276M1JLAE054CT-ND, Leakage Current=340uA, Manufacturer=KEMET, Mouser Part Number=80-A768KE276M1JLAE54, Operating Temperature Range="-55°C to +125°C", Tolerance_%=20%, ValueDisplayed=27uF
C14: library part CMP-0006196-2, "CAP, CERM, 100 pF, 50 V, +/- 1%, C0G/NP0, 0402", Cap_Case=0402, Manufacturer=AVX, Supplier Part Number 1=478-3658-1-ND, TempCo=C0G/NP0, Tolerance_%=1%, Value1=Unknown, Value2=50V, ValueDisplayed=100pF
C22 C38: library part CMP-0006486-2, "CAP, CERM, 680 pF, 50 V, +/- 5%, C0G/NP0, 0402", Cap_Case=0402, Manufacturer=MuRata, Supplier Part Number 1=490-3240-1-ND, TempCo=C0G/NP0, Tolerance_%=5%, Value1=Unknown, Value2=50V, ValueDisplayed=680pF
C23 C39: library part CMP-0006493-2, "CAP, CERM, 820 pF, 50 V, +/- 5%, C0G/NP0, 0402", Cap_Case=0402, Manufacturer=MuRata, Supplier Part Number 1=490-3242-1-ND, TempCo=C0G/NP0, Tolerance_%=5%, Value1=Unknown, Value2=50V, ValueDisplayed=820pF
C25: library part CMP-0006485-2, "CAP, CERM, 68 pF, 50 V, +/- 5%, C0G/NP0, 0402", Cap_Case=0402, Manufacturer=MuRata, Supplier Part Number 1=81-GRM1555C1H680JA1D, TempCo=C0G/NP0, Tolerance_%=5%, Value1=Unknown, Value2=50V, ValueDisplayed=68pF
C26 C27: library part CMP-0092433-2, "Multi-Layer Ceramic Capacitor 22uF 10V X5R ±20% 0603 Paper T/R", Manufacturer=Murata, Operating Temperature Range="-55°C to +85°C", TempCo=15%, Temperature Characteristic=X5R, Tolerance_%=20%, ValueDisplayed=22uF
C30: library part CMP-0008176-2, "CAP, CERM, 680 pF, 100 V, +/- 5%, C0G/NP0, 0805", Cap_Case=0805, Manufacturer=MuRata, Supplier Part Number 1=490-1613-1-ND, TempCo=C0G/NP0, Tolerance_%=5%, Value1=Unknown, Value2=100V, ValueDisplayed=680pF
C31 C33: library part CMP-0007469-4, "CAP, CERM, 0.1 uF, 100 V, +/- 10%, X7R, 0603", Cap_Case=0603, Manufacturer=MuRata, Supplier Part Number 1=490-3285-1-ND, TempCo=X7R, Tolerance_%=10%, Value1=Unknown, Value2=100V, ValueDisplayed=0.1uF
C32: library part CMP-0008168-2, "CAP, CERM, 1000 pF, 100 V, +/- 5%, C0G/NP0, 0805", Cap_Case=0805, Manufacturer=MuRata, Supplier Part Number 1=490-1614-1-ND, TempCo=C0G/NP0, Tolerance_%=5%, Value1=Unknown, Value2=100V, ValueDisplayed=1000pF
C34: library part CMP-0006421-2, "CAP, CERM, 150 pF, 50 V, +/- 5%, C0G/NP0, 0402", Cap_Case=0402, Manufacturer=MuRata, Supplier Part Number 1=490-3229-1-ND, TempCo=C0G/NP0, Tolerance_%=5%, Value1=Unknown, Value2=50V, ValueDisplayed=150pF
